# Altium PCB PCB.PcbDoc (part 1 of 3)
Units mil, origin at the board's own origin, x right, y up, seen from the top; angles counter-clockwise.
Board outline 5645.41 x 3720.47 mil, 4 copper layers (Top Layer, Signal Layer 1, Signal Layer 2, Bottom Layer), stack 61.2 mil thick; 253 components, 113 nets, 631 pads, 211 vias.
Unrouted connection lines stored in the file: 1.
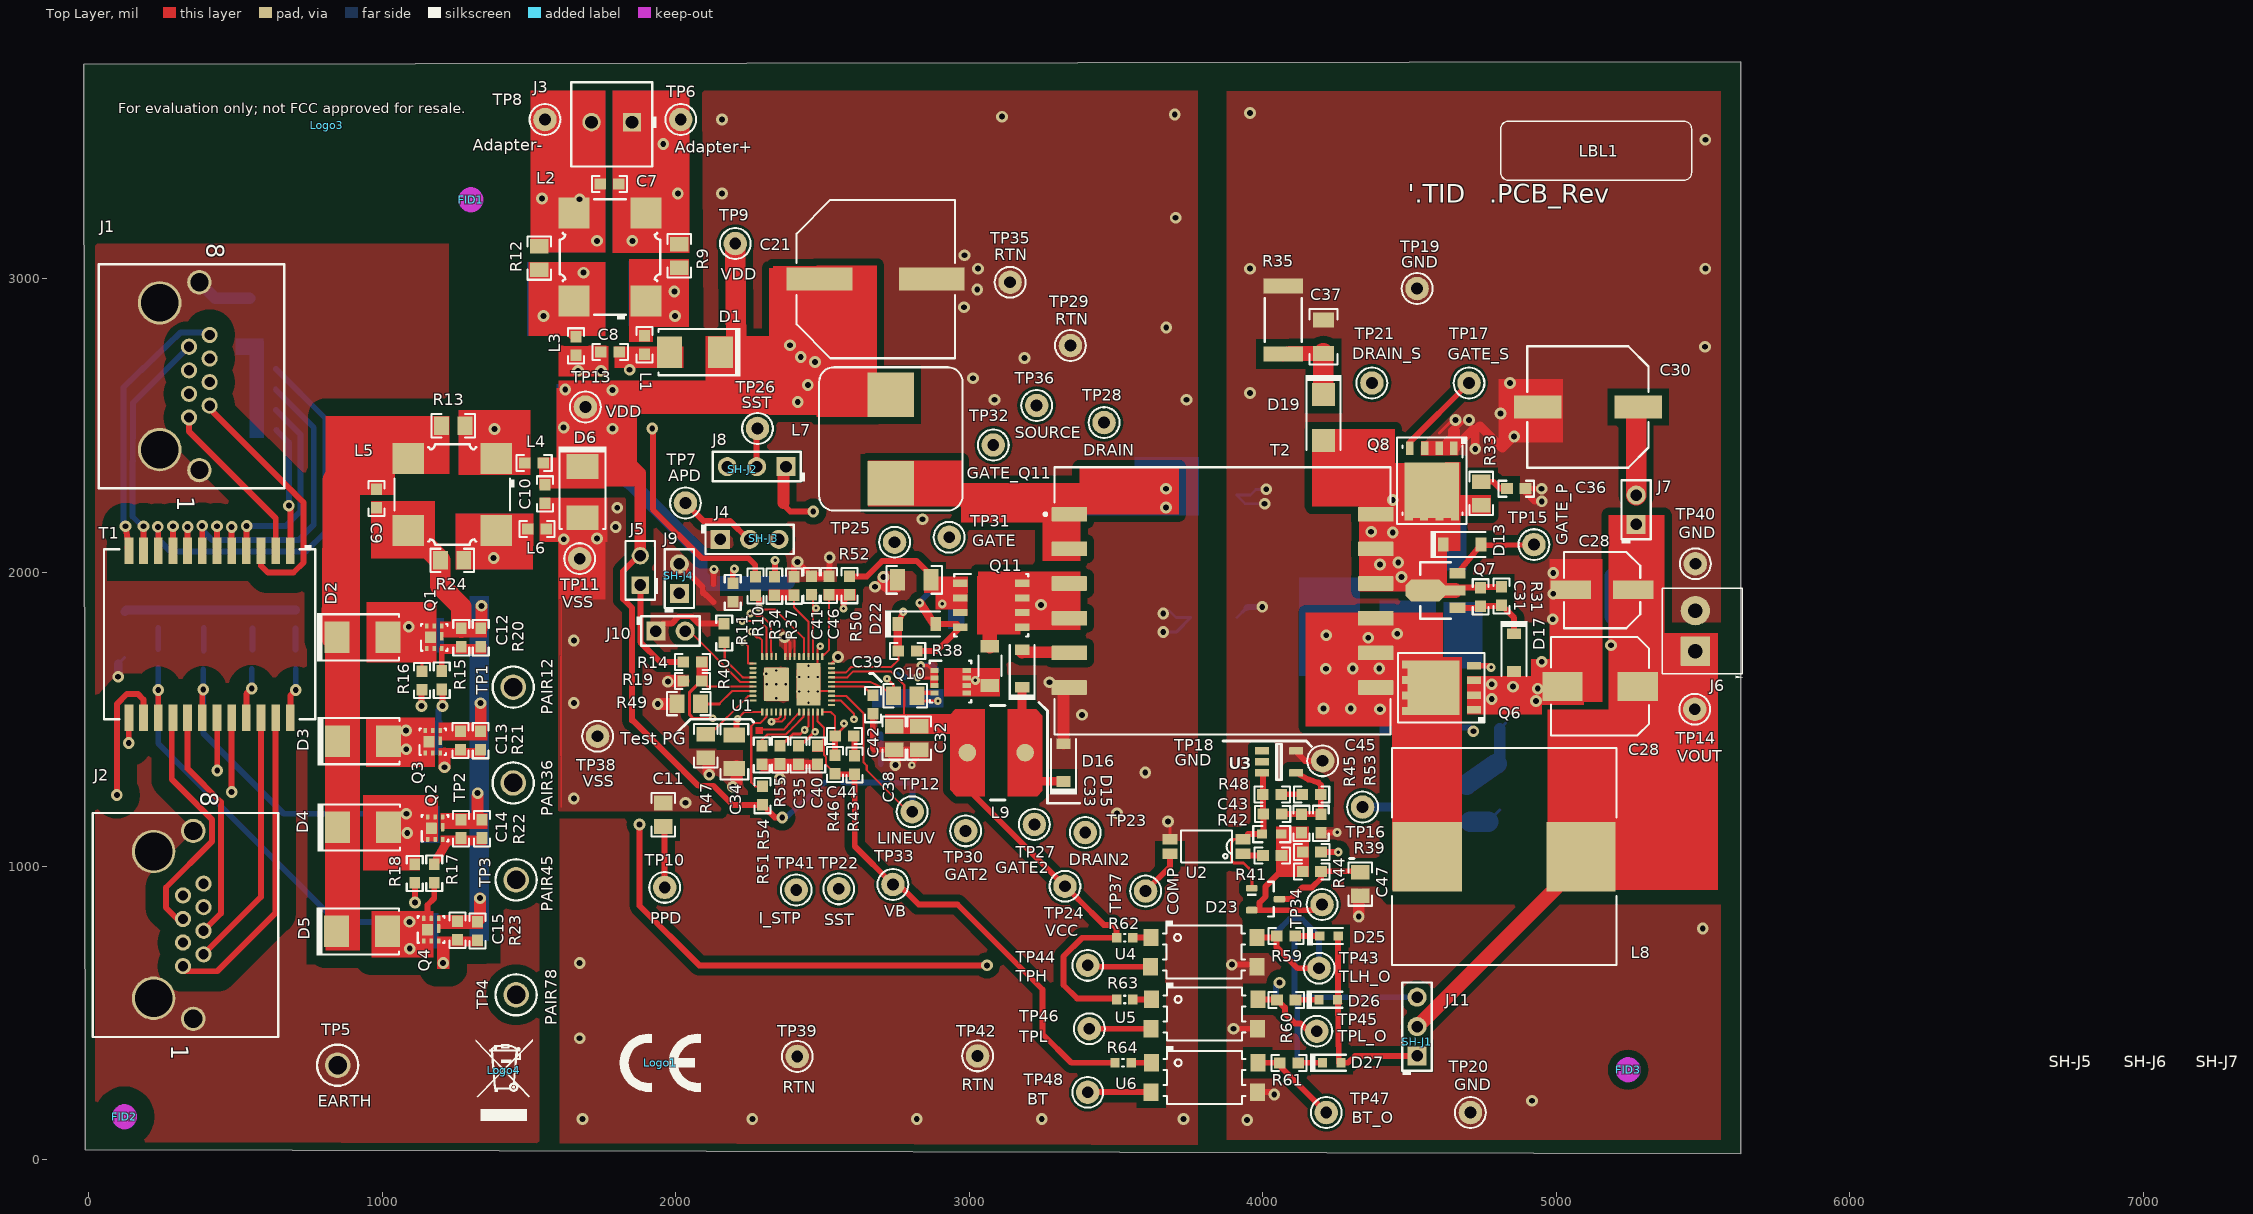
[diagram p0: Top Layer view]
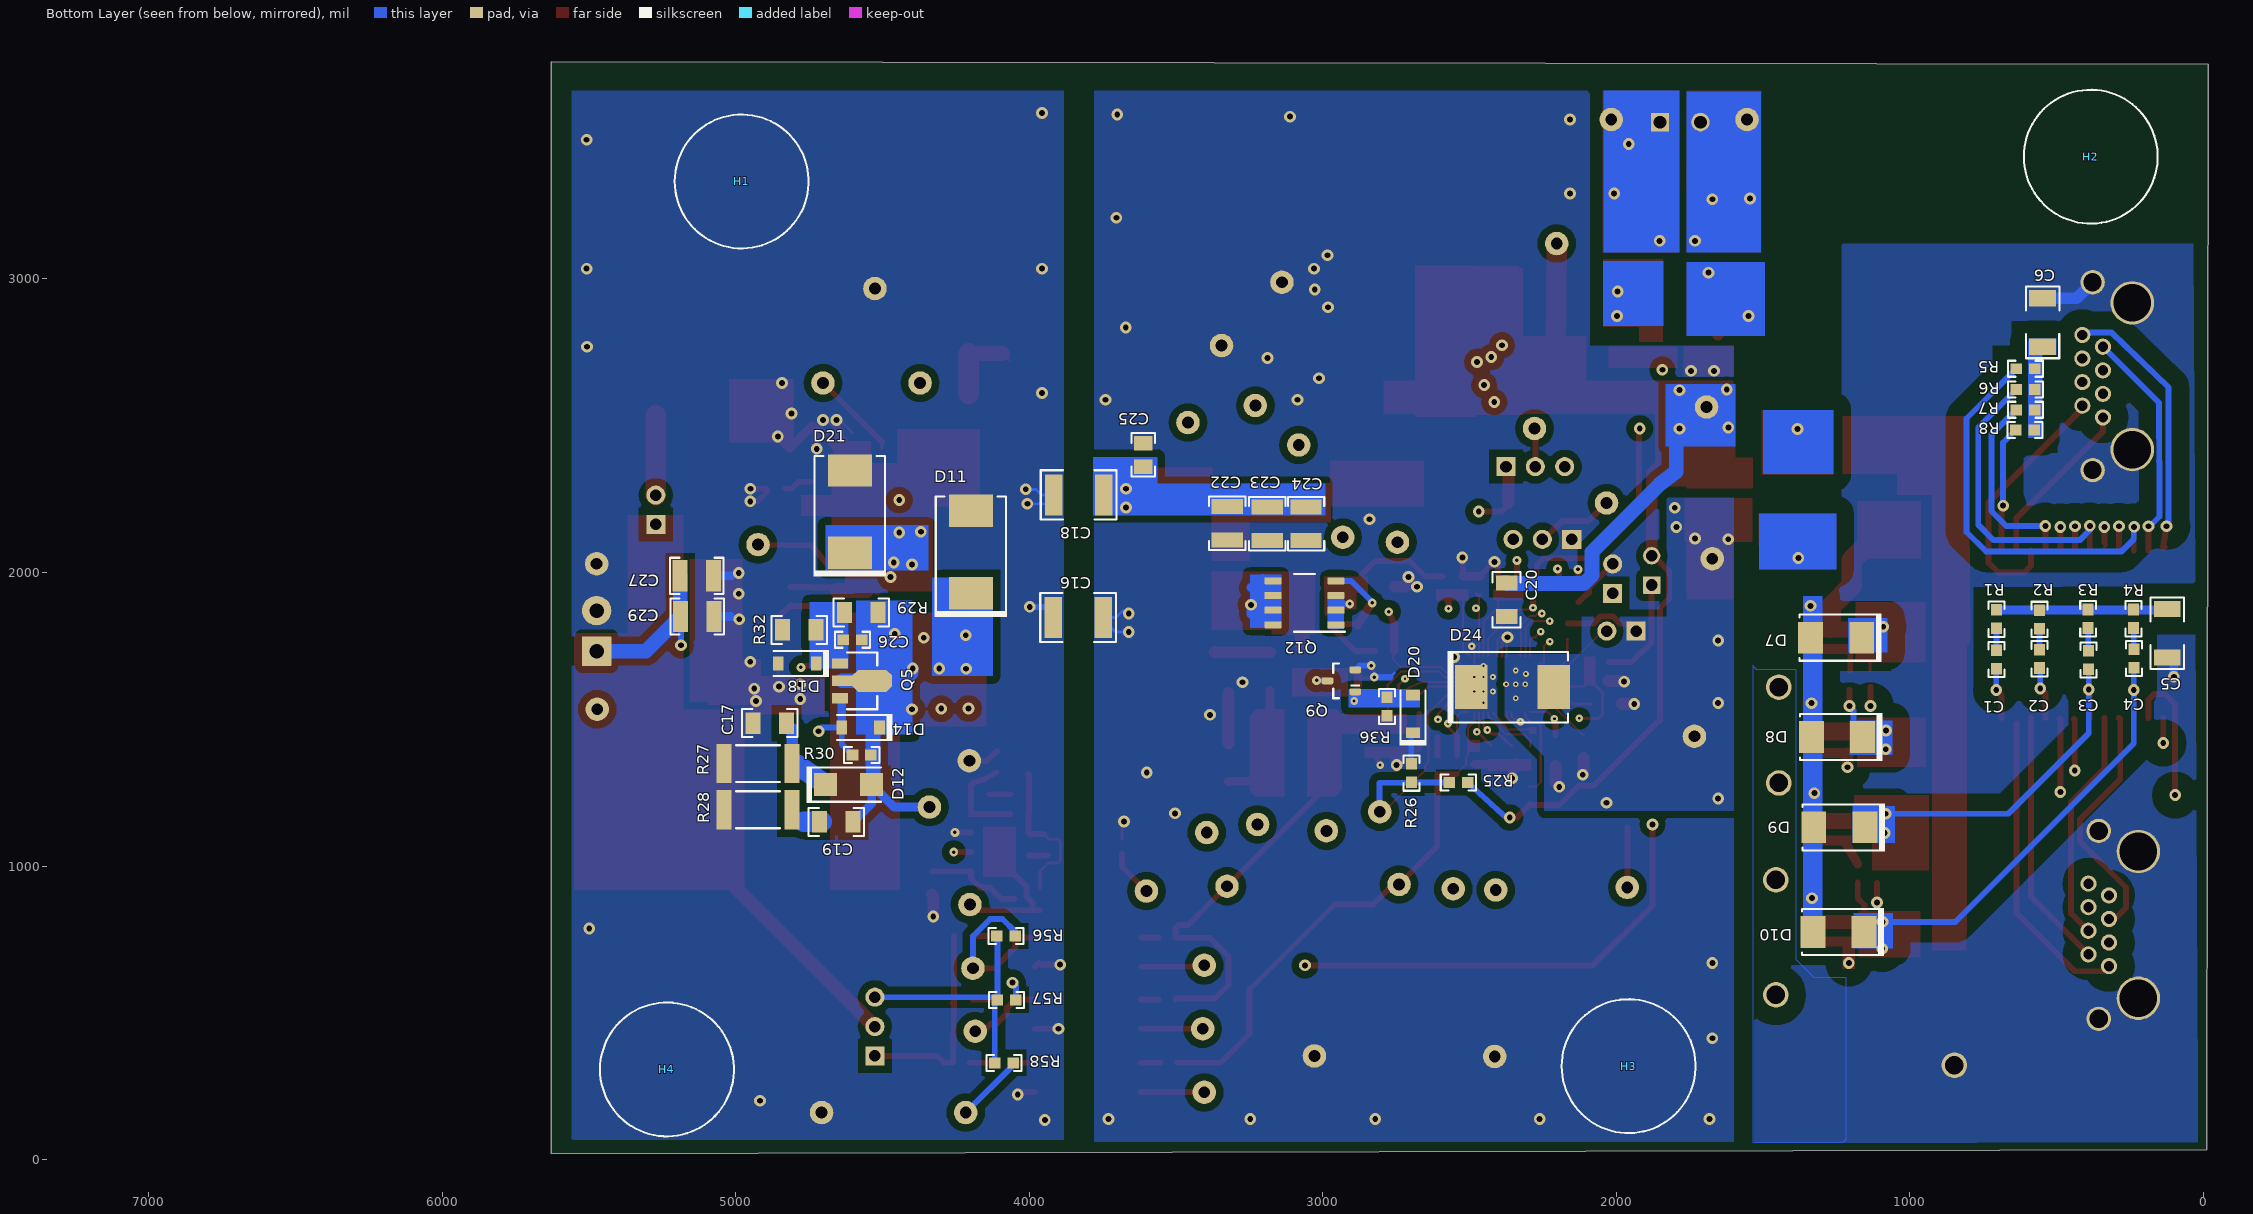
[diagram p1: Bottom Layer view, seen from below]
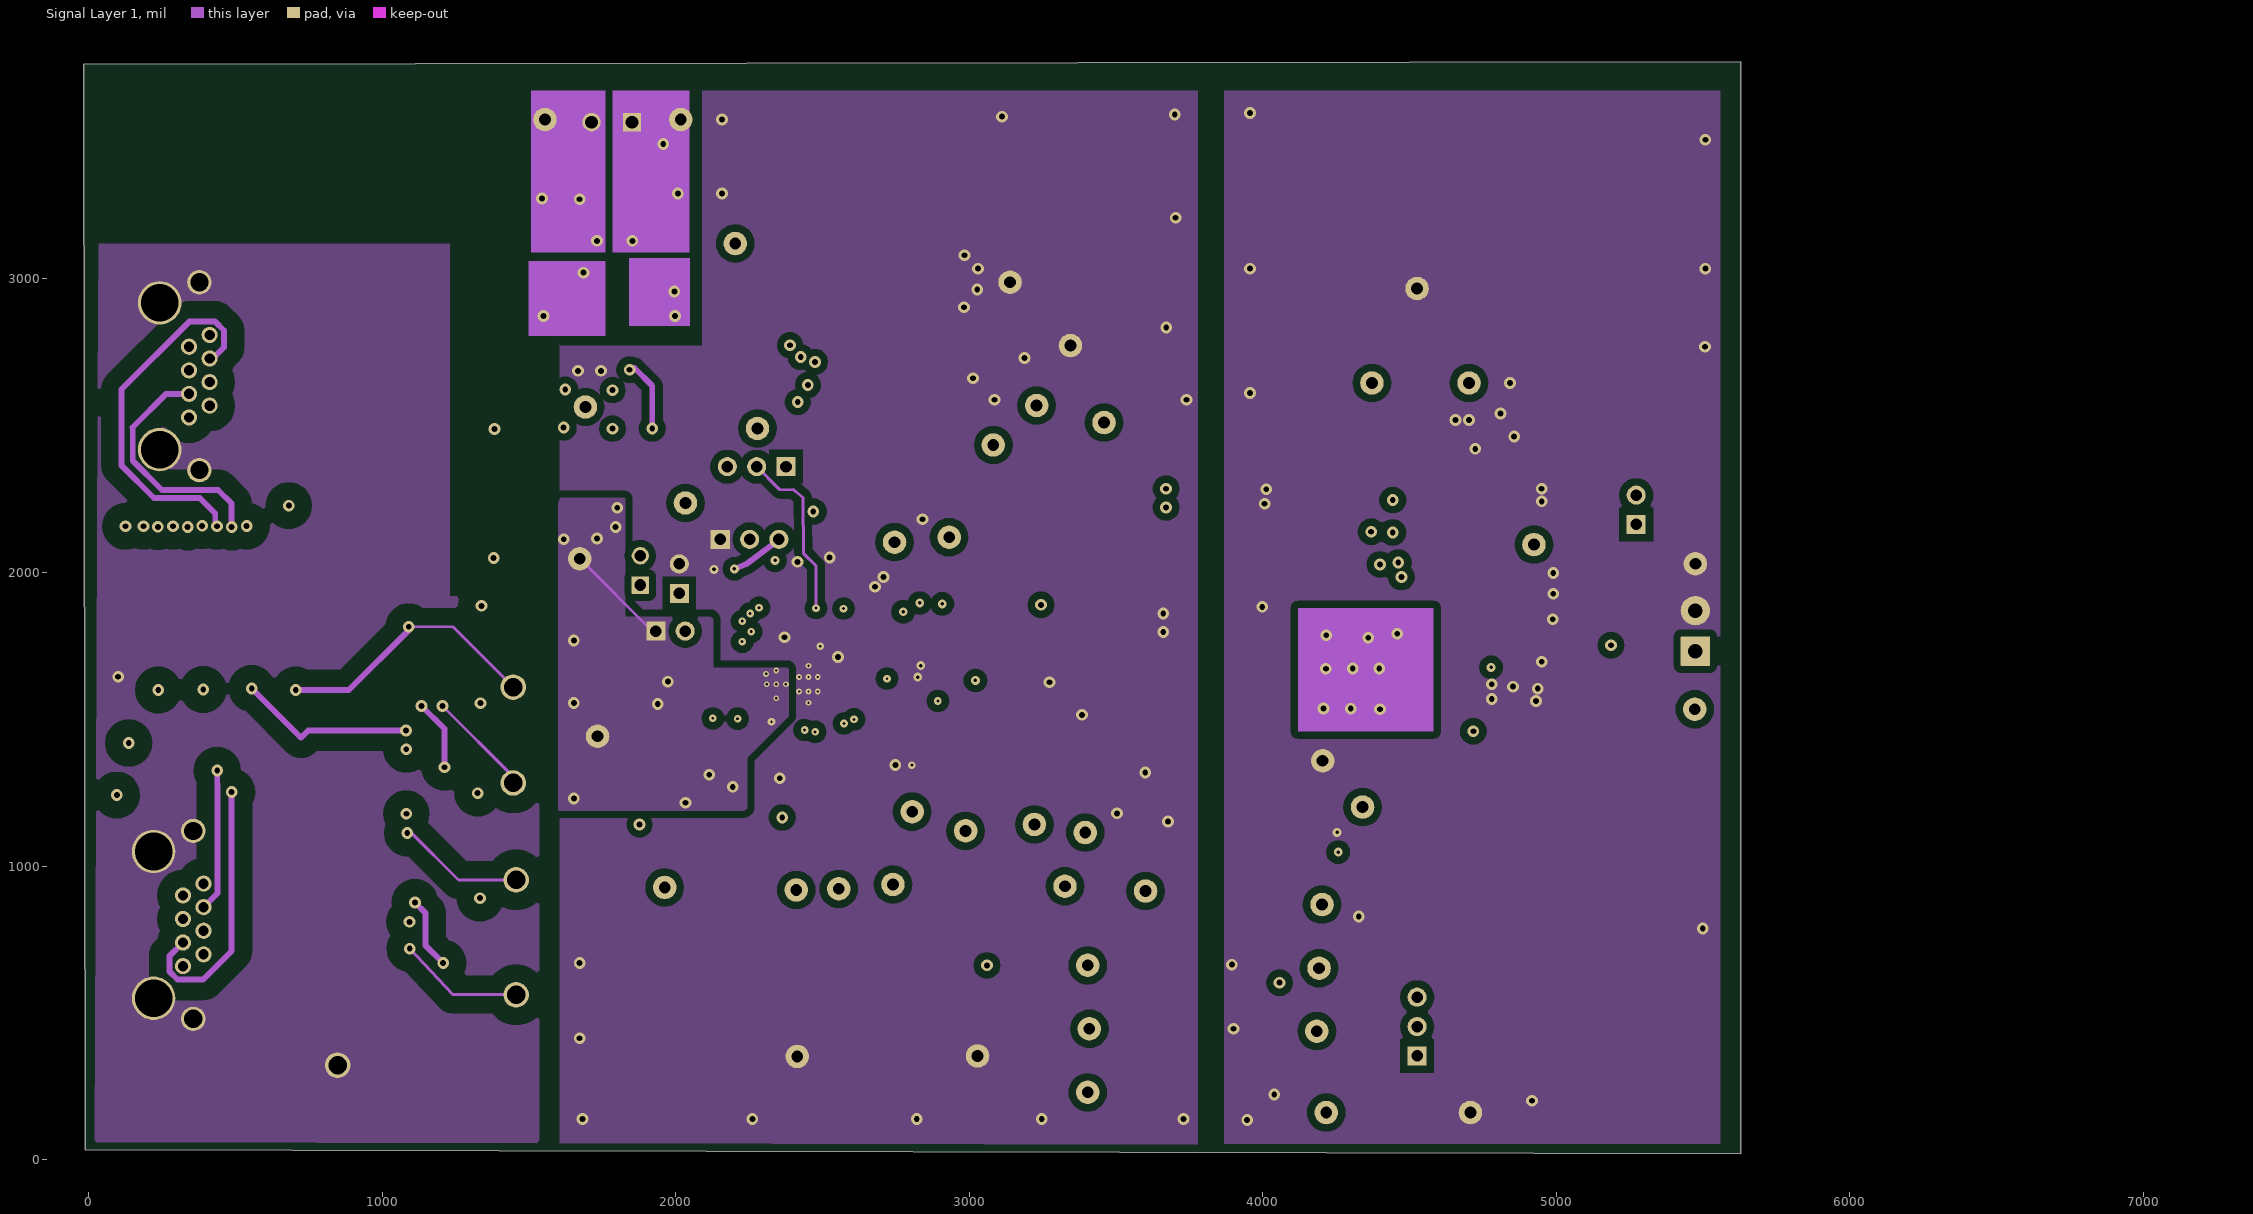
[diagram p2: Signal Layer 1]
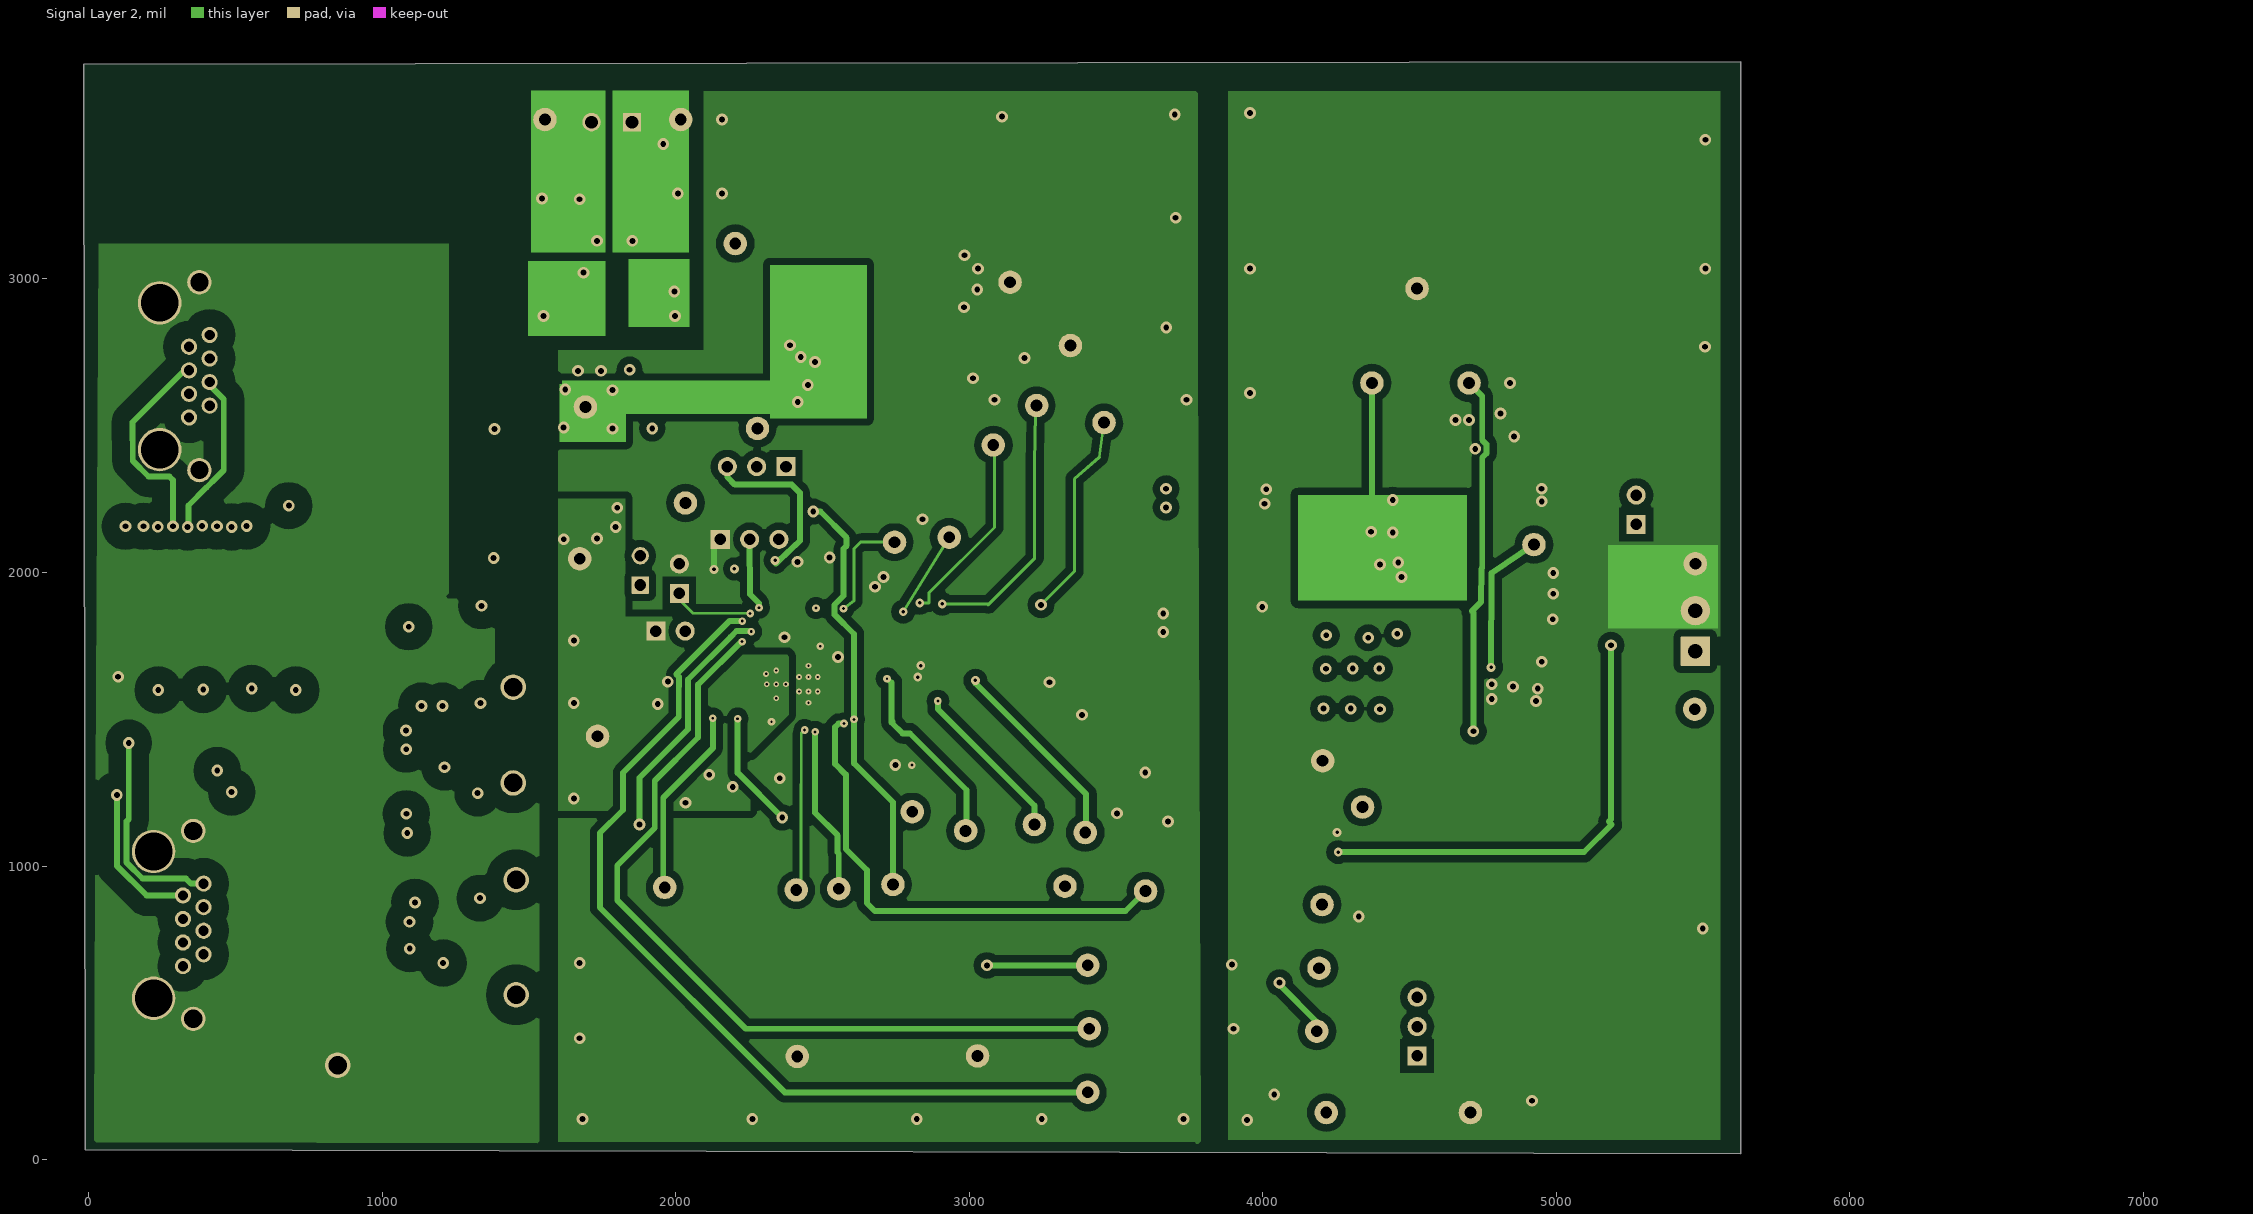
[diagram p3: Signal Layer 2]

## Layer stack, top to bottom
Top Solder: solder mask 0.4, Solder Resist, Dk 3.5
Top Layer: signal copper 2.8
Dielectric 1: prepreg 15, FR-4, Dk 4.8
Signal Layer 1: signal copper 2.8
Dielectric 2: core 20, FR-4, Dk 4.2
Signal Layer 2: signal copper 2.8
Dielectric 3: prepreg 15, FR-4, Dk 4.2
Bottom Layer: signal copper 2.8
Bottom Solder: solder mask 0.4, Solder Resist, Dk 3.5

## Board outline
-10.71,33.26 -16.35,3732 5629.06,3740.16 5629.06,19.68

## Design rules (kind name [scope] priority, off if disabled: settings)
AcuteAngle [All] p1: minimum=4.50000000000000E+0001 checktracksonly=FALSE
AssemblyTestPointUsage [All] p1: valid=2
BoardOutlineClearance BoardOutlineClearance_MountingHoles [OnCopper and InComponentClass('Mounting Holes')] p1: gap=39.37 ignorepadtopadclearanceinfootprint=FALSE
BoardOutlineClearance BoardOutlineClearance_Poly [OnCopper and IsPoly] p2: gap=25 ignorepadtopadclearanceinfootprint=FALSE
BoardOutlineClearance [OnCopper and Not InComponentClass('Logo') and not InComponentClass('FiducialMark') and not InRegion(1000,500,4000,800) and not InPoly] p3: gap=75 ignorepadtopadclearanceinfootprint=FALSE
Clearance Clearance_14 [InNamedPolygon('BOTTOM_LAYER_EARTH_P016')] p1: gap=60 ignorepadtopadclearanceinfootprint=FALSE
Clearance Clearance_13 [InNamedPolygon('SIGNAL_LAYER_1_EARTH_P014')] p2: gap=60 ignorepadtopadclearanceinfootprint=FALSE
Clearance Clearance_12 [InNamedPolygon('BOTTOM_LAYER_EARTH_P013')] p3: gap=60 ignorepadtopadclearanceinfootprint=FALSE
Clearance Clearance_11 [InNamedPolygon('SIGNAL_LAYER_2_EARTH_P012')] p4: gap=60 ignorepadtopadclearanceinfootprint=FALSE
Clearance Clearance_10 [InNamedPolygon('TOP_LAYER_EARTH_P015')] p5: gap=60 ignorepadtopadclearanceinfootprint=FALSE
Clearance Clearance_9 [InNamedPolygon('TOP_LAYER_EARTH_P015')] p6: gap=60 ignorepadtopadclearanceinfootprint=FALSE
Clearance Clearance_8 [InNamedPolygon('TOP_LAYER_EARTH_P015')] p7: gap=10 ignorepadtopadclearanceinfootprint=FALSE except(0: Arc-Hole Track-Hole SMDPad-Hole THPad-Hole Via-Hole Fill-Hole Poly-Hole Region-Hole Text-Hole)
Clearance "60 Mils_1" [InNamedPolygon('SIGNAL_LAYER_1_EARTH_P014')] p8: gap=10 ignorepadtopadclearanceinfootprint=FALSE except(0: Arc-Hole Track-Hole SMDPad-Hole THPad-Hole Via-Hole Fill-Hole Poly-Hole Region-Hole Text-Hole)
Clearance "60 Mils" [InNamedPolygon('SIGNAL_LAYER_2_EARTH_P012')] p9: gap=10 ignorepadtopadclearanceinfootprint=FALSE except(0: Arc-Hole Track-Hole SMDPad-Hole THPad-Hole Via-Hole Fill-Hole Poly-Hole Region-Hole Text-Hole)
Clearance Clearance_7 [InNamedPolygon('BOTTOM_LAYER_EARTH_P032')] p10: gap=10 ignorepadtopadclearanceinfootprint=FALSE except(0: Arc-Hole Track-Hole SMDPad-Hole THPad-Hole Via-Hole Fill-Hole Poly-Hole Region-Hole Text-Hole)
Clearance Clearance_6 [InNamedPolygon('TOP_LAYER_EARTH_P030')] p11: gap=10 ignorepadtopadclearanceinfootprint=FALSE except(0: Arc-Hole Track-Hole SMDPad-Hole THPad-Hole Via-Hole Fill-Hole Poly-Hole Region-Hole Text-Hole)
Clearance Clearance_5 [InNamedPolygon('BOTTOM_LAYER_EARTH_P032')] p12: gap=10 ignorepadtopadclearanceinfootprint=FALSE except(0: Arc-Hole Track-Hole SMDPad-Hole THPad-Hole Via-Hole Fill-Hole Poly-Hole Region-Hole Text-Hole)
Clearance Clearance_4 [InNamedPolygon('TOP_LAYER_EARTH_P030')] p13: gap=10 ignorepadtopadclearanceinfootprint=FALSE except(0: Arc-Hole Track-Hole SMDPad-Hole THPad-Hole Via-Hole Fill-Hole Poly-Hole Region-Hole Text-Hole)
Clearance Clearance_3 [InNamedPolygon('SIGNAL_LAYER_1_EARTH_P014')] p14: gap=10 ignorepadtopadclearanceinfootprint=FALSE except(0: Arc-Hole Track-Hole SMDPad-Hole THPad-Hole Via-Hole Fill-Hole Poly-Hole Region-Hole Text-Hole)
Clearance Clearance_2 [InNamedPolygon('SIGNAL_LAYER_2_EARTH_P012')] p15: gap=10 ignorepadtopadclearanceinfootprint=FALSE except(0: Arc-Hole Track-Hole SMDPad-Hole THPad-Hole Via-Hole Fill-Hole Poly-Hole Region-Hole Text-Hole)
Clearance Clearance_1 [InNamedPolygon('BOTTOM_LAYER_EARTH_P032')] p16: gap=10 ignorepadtopadclearanceinfootprint=FALSE except(0: Arc-Hole Track-Hole SMDPad-Hole THPad-Hole Via-Hole Fill-Hole Poly-Hole Region-Hole Text-Hole)
Clearance Clearance_Keepouts [((IsTrack Or IsArc) And Not InPoly) And IsFree and IsKeepOut vs ((IsTrack Or IsArc) And Not InPoly) And IsFree and IsKeepOut] p17: gap=0 ignorepadtopadclearanceinfootprint=FALSE
Clearance Clearance_Poly [InPolygon] p18: gap=25 ignorepadtopadclearanceinfootprint=TRUE
Clearance Clearance_FiducialMark [IsKeepOut and InComponentClass('FiducialMark') vs IsPad and InComponentClass('FiducialMark')] p19: gap=0 ignorepadtopadclearanceinfootprint=FALSE
Clearance [All] p20: gap=7.87 ignorepadtopadclearanceinfootprint=TRUE
ComponentClearance ComponentClearance_MountingHoles_FiducialMarks [InComponentClass('Mounting Holes') vs InComponentClass('FiducialMark')] p1: gap=50 collisioncheckmode=3 verticalgap=10 showdistances=FALSE
ComponentClearance ComponentClearance_Shunt [InComponentClass('Header') vs InComponentClass('Shunt')] p2: gap=0 collisioncheckmode=3 verticalgap=0 showdistances=FALSE
ComponentClearance ComponentClearance_Logo [InComponentClass('Logo')] p3: gap=50 collisioncheckmode=3 verticalgap=10 showdistances=FALSE
ComponentClearance ComponentClearance_ScrewToNut [(HasFootprint('NY PMS 440 0025 PH')) vs (HasFootprint('Keystone_1902C'))] p4: gap=5 collisioncheckmode=3 verticalgap=10 showdistances=FALSE
ComponentClearance ComponentClearance_MountingHoles [InComponentClass('Mounting Holes')] p5: gap=250 collisioncheckmode=3 verticalgap=100000 showdistances=FALSE
ComponentClearance ComponentClearance_SmallPassives [HasFootprint('0201*') or HasFootprint('0402*') or HasFootprint('0508') or HasFootprint('0603*') or HasFootprint('0612') or HasFootprint('0805*') or HasFootprint('0815*') or HasFootprint('0830*') or HasFootprint('1206*') or HasFootprint('1210*') or HasFootprint('1808*') or HasFootprint('1812*') or HasFootprint('1825*') or HasFootprint('2010*') or HasFootprint('2220*') or HasFootprint('2225*') or HasFootprint('2512*') or HasFootprint('2728*') or HasFootprint('3518*') vs HasFootprint('0201*') or HasFootprint('0402*') or HasFootprint('0508') or HasFootprint('0603*') or HasFootprint('0612') or HasFootprint('0805*') or HasFootprint('0815*') or HasFootprint('0830*') or HasFootprint('1206*') or HasFootprint('1210*') or HasFootprint('1808*') or HasFootprint('1812*') or HasFootprint('1825*') or HasFootprint('2010*') or HasFootprint('2220*') or HasFootprint('2225*') or HasFootprint('2512*') or HasFootprint('2728*') or HasFootprint('3518*')] p6: gap=14.96 collisioncheckmode=3 verticalgap=10 showdistances=FALSE
ComponentClearance ComponentClearance_THtoSMT [IsThruComponent vs IsSMTComponent] p7: gap=40 collisioncheckmode=3 verticalgap=30 showdistances=FALSE
ComponentClearance ComponentClearance_THtoTH [IsThruComponent vs IsThruComponent] p8: gap=30 collisioncheckmode=3 verticalgap=30 showdistances=FALSE
ComponentClearance [All] p9: gap=30 collisioncheckmode=3 verticalgap=10 showdistances=FALSE
DiffPairsRouting [All] p1: maxlimit=100 minlimit=10 mostfreqgap=10 toplayer_minwidth=15 toplayer_maxwidth=15 toplayer_prefwidth=15 midlayer1_minwidth=15 midlayer1_maxwidth=15 midlayer1_prefwidth=15 midlayer2_minwidth=15 midlayer2_maxwidth=15 midlayer2_prefwidth=15 bottomlayer_minwidth=15 bottomlayer_maxwidth=15 bottomlayer_prefwidth=15 maxuncoupledlength=1000
FabricationTestPointUsage TestPointUsage [All] p1: valid=2 allowmultiple=FALSE
FabricationTestpoint Testpoint [All] p1: side=3 testpointundercomponent=TRUE minsize=40 maxsize=100 preferedsize=60 minholesize=0 maxholesize=40 preferedholesize=32 testpointgrid=1 allowsidetop=TRUE allowsidebottom=TRUE usegrid=TRUE gridtolerance=0.01
FanoutControl Fanout_LCC [IsLCC] p1: bgadir=Out bgaviamode=Centered fanoutstyle=Auto fanoutdirection=Alternating viagrid=1 // Fanout_LCC (Default Rule)
FanoutControl Fanout_BGA [IsBGA] p2: bgadir=Out bgaviamode=Centered fanoutstyle=Auto fanoutdirection=Alternating viagrid=1 // Fanout_BGA (Default Rule)
FanoutControl Fanout_Default [All] p4: bgadir=Out bgaviamode=Centered fanoutstyle=Auto fanoutdirection=Alternating viagrid=1 // Fanout_Default (Default Rule)
FanoutControl Fanout_Small [(CompPinCount < 5)] p5: bgadir=Out bgaviamode=Centered fanoutstyle=Auto fanoutdirection=OutThenIn viagrid=1 // Fanout_Small (Default Rule)
HoleSize [All] p1: absolutevalues=TRUE maxlimit=251 minlimit=7.87 maxpercent=80.000 minpercent=20.000
MinimumAnnularRing MinimumAnnularRing_ThermalPadVias [IsVia and InAnyComponent] p1: minimumring=5.91
MinimumAnnularRing [All] p2: minimumring=7.87
MinimumSolderMaskSliver MinimumSolderMaskSliver_Logo [InComponentClass('Logo') vs InComponentClass('Logo')] p1: minsoldermaskwidth=0.7
MinimumSolderMaskSliver [All] p2: minsoldermaskwidth=3.94
PlaneConnect [All] p1: planeconnectstyle=Relief reliefexpansion=10 reliefentries=4 reliefconductorwidth=10 reliefairgap=10
PolygonConnect [All] p1: connectstyle=Direct reliefconductorwidth=10 reliefentries=4 polygonreliefangle="90 Angle" airgapwidth=10
RoutingVias ThermalPadVias [IsVia and InAnyComponent] p1: holewidth=7.87 width=19.68 viastyle="Through Hole" minholewidth=7.87 minwidth=19.68 maxholewidth=12.99 maxwidth=23.62
RoutingVias [All] p2: holewidth=16 width=34 viastyle="Through Hole" minholewidth=7.87 minwidth=26 maxholewidth=40 maxwidth=65
SilkToBoardRegionClearance [Not ((IsComment or IsDesignator) And (Hide <> 'False')) and not InRegion(1000,500,4000,800)] p1:
SilkToSilkClearance SilkToSilkClearance_Pb-FreeLogo [(HasFootprint('Pb-Free_Overlay_Medium') OR HasFootprint('Pb-Free_Overlay_Small')) vs (HasFootprint('Pb-Free_Overlay_Medium') OR HasFootprint('Pb-Free_Overlay_Small'))] p1: silktosilkclearance=0
SilkToSilkClearance [All] p2: silktosilkclearance=3.94
SilkToSolderMaskClearance SilkToComponentPadClearance [(IsPad or IsFill or IsRegion) and InAnycomponent] p1: minsilkscreentomaskgap=5 clearancetoexposedcopper=TRUE
SilkToSolderMaskClearance "Silk to Solder Mask Opening" [All] p2: minsilkscreentomaskgap=3.94 clearancetoexposedcopper=FALSE
SolderMaskExpansion [All] p1: expansion=1.97
UnRoutedNet [All] p1: checkbadconnections=TRUE
Width [All] p1: maxlimit=100 minlimit=6 preferedwidth=10 checkconnectedcopper=TRUE
14 further rules are at their usual default settings.

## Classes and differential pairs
component class Shunt: SH-J1 SH-J2 SH-J3 SH-J4 SH-J5 SH-J6 SH-J7
component class "TPS23730 Page 1 Input Power": C1 C2 C3 C4 C5 C6 C7 C8 C9 C10 C11 C12 C13 C14 C15 D1 D2 D3 D4 D5 D6 D7 D8 D9 D10 J1 J2 J3 J4 J5 L1 L2 L3 L4 L5 L6 Q1 Q2 Q3 Q4 R1 R2 R3 R4 R5 R6 R7 R8 R9 R10 R11 R12 R13 R14 R15 R16 R17 R18 R19 R20 R21 R22 R23 R24 T1 TP1 TP2 TP3 TP4 TP5 TP6 TP7 TP8 TP9 TP10 TP11
component class "Power Stage": C16 C17 C18 C19 C20 C21 C22 C23 C24 C25 C26 C27 C29 C30 C31 C32 C33 C34 C35 C36 C37 C38 C39 C40 C41 C42 C43 C44 C45 C46 C47 D11 D12 D13 D14 D15 D16 D17 D18 D19 D20 D21 D22 D23 D24 D25 D26 D27 J6 J7 J8 J9 J10 J11 L7 L8 L9 Q5 Q6 Q7 Q9 Q10 Q11 Q12 R25 R26 R27 R28 R29 R30 R31 R32 R33 R34 R35 R36 R37 R38 R39 R40 R41 R42 R43 R44 R45 R46 R47 R48 R49 R50 R51 R52 R53 R54 R55 R56 R57 R58 R59 R60 R61 R62 R63 R64 TP12 TP13 TP14 TP15 TP16 TP17 TP18 TP19 TP20 TP21 TP22 TP23 TP24 TP25 TP26 TP27 TP28 TP29 TP30 TP31 TP32 TP33 TP34 TP35 TP36 TP37 TP38 TP39 TP40 TP41 TP42 TP43 TP44 TP45 TP46 TP47 TP48 U1 U2 U4 U5 U6
component class Header: J4 J5 J7 J8 J9 J10 J11
component class Hardware: FID1 FID2 FID3 H1 H2 H3 H4 LBL1 Logo1 Logo3 Logo4 SH-J1 SH-J2 SH-J3 SH-J4 SH-J5 SH-J6 SH-J7 ZZ1 ZZ2 ZZ3 ZZ4
component class FiducialMark: FID1 FID2 FID3
component class AssemblyNote: ZZ1 ZZ2 ZZ3 ZZ4
component class Label: LBL1

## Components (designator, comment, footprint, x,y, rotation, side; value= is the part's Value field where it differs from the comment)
C1 "CGA3E2X7R2A103K080AA" 0603 705.58,1703.55 r270 bottom value=0.01uF
C2 "CGA3E2X7R2A103K080AA" 0603 559.05,1706.06 r270 bottom value=0.01uF
C3 "CGA3E2X7R2A103K080AA" 0603 391.73,1702.14 r270 bottom value=0.01uF
C4 "CGA3E2X7R2A103K080AA" 0603 236.43,1707.1 r270 bottom value=0.01uF
C5 "GR442QR73D102KW01L" 1808 123.15,1793.21 r90 bottom value=1000pF
C6 "GR442QR73D102KW01L" 1808 548.29,2851.9 r270 bottom value=1000pF
C7 "C1608X7R2A102K080AA" 0603 1774.96,3323.43 r180 top value=1000pF
C8 "C1608X7R2A102K080AA" 0603 1777.28,2750.6 r180 top value=1000pF
C9 "C1608X7R2A102K080AA" 0603 981,2252.22 r270 top value=1000pF
C10 "C1608X7R2A102K080AA" 0603 1554.47,2267.96 r270 top value=1000pF
C11 "08051C471KAT2A" 0805_HV 1958.66,1174.89 r90 top value=470pF
C12 "885012006060" 0603 1269.83,1777.85 r90 top value=330pF
C13 "885012006060" 0603 1267.4,1427.58 r90 top value=330pF
C14 "885012006060" 0603 1269.22,1126.86 r90 top value=330pF
C15 "885012006060" 0603 1256.76,780.9 r90 top value=330pF
C16 "C4532X7R3D222K130KA" 1812_HV 3834.05,1846.6 r180 bottom value=2200pF
C17 "CGA5H2X7R2A473K115AA" 1206 4884.22,1486.71 r180 bottom value=0.047uF
C18 "C4532X7R3D222K130KA" 1812_HV 3832.29,2264.38 r180 bottom value=2200pF
C19 "12061C102KAT2A" 1206 4657.49,1150.17 r180 bottom value=1000pF
C20 "GRM319R72A104KA01D" 1206 2373.91,1907.27 r270 bottom value=0.1uF
C21 "EEV-FK2A680Q" SM_RADIAL_H13 2681.9,2999.72 r0 top value=68uF
C22 "GRM32ER72A225KA35L" 1210_270 3325.7,2167.32 r270 bottom value=2.2uF
C23 "GRM32ER72A225KA35L" 1210_270 3189.76,2166.54 r270 bottom value=2.2uF
C24 "GRM32ER72A225KA35L" 1210_270 3057.24,2166.54 r270 bottom value=2.2uF
C25 "GRM21BR72A104KAC4L" 0805_HV 3612.2,2400.63 r90 bottom value=0.1uF
C26 "06033C101KAT2A" 0603 4602.79,1770.91 r180 bottom value=100pF
C27 "GRM32EC70J107ME15L" 1210_270 5132.73,1988.59 r0 bottom value=100uF
C27 "GMK325BJ226MM-P" 1210 5132.73,1988.59 r0 bottom value=22uF
C28 "UUD0J471MNL1GS" SM_RADIAL_8MM 5149.73,1612.23 r180 top value=470uF
C28 "16SVP39M" SM_RADIAL_6.3AMM 5156.7,1940.6 r180 top value=39uF
C29 "GRM32EC70J107ME15L" 1210_270 5132.01,1849.96 r0 bottom value=100uF
C29 "GMK325BJ226MM-P" 1210 5132.01,1849.96 r0 bottom value=22uF
C30 "EEEFPE561UAP" Panasonic_G 5108.27,2563.86 r180 top value=560uF
C31 "06033C101KAT2A" 0603 4743.12,1917.05 r270 top value=100pF
C32 "GRM21BR71E105KA99L" 0805_HV 2830.91,1436.08 r270 top value=1uF
C33 "GRM31CR72E473KW03L" 1206_180 3070.8,1682.21 r270 top value=0.047uF
C34 "GRM319R72A104KA01D" 1206 2200.07,1388.67 r270 top value=0.1uF
C35 "GRM188R71H473KA61D" 0603 2419.04,1377.9 r90 top value=0.047uF
C36 "CGA3E2X7R2A102K080AA" 0603 4864.17,2285.39 r180 top value=1000pF
C37 "CGA5H2X7R2A473K115AA" 1206 4207.38,2803.15 r270 top value=0.047uF
C38 "GCM21BR71H104KA37K" 0805_HV 2744.29,1436.08 r270 top value=0.1uF
C39 "C2012X5R1H224K125AA" 0805_HV 2782.68,1580.63 r180 top value=0.22uF
C40 "CGA3E2X7R1E104K080AA" 0603 2482.83,1378.31 r90 top value=0.1uF
C41 "C0603C222K5RAC" 0603 2463.64,1955.69 r90 top value=2200pF
C42 "C0603C104J3RACTU" 0603 2671.97,1549.87 r90 top value=0.1uF
C43 "06033C101KAT2A" 0603 4034.25,1177.37 r0 top value=100pF
C44 "GRM188R71C683KA01D" 0603 2575.17,1442.85 r0 top value=0.068uF
C45 "GRM188R71H392KA01D" 0603 4167.12,1244.3 r180 top value=3900pF
C46 "GRM1885C1H470JA01D" 0603 2523.35,1955.69 r90 top value=47pF
C47 "C2012X7R1H105K125AB" 0805_HV 4332.52,938.68 r270 top value=1uF
D1 "CMP-0028397-2" SMB 2066.78,2750.6 r180 top value=100V
D2 "B2100-13-F" SMB 932.75,1779.2 r0 top value=100V
D3 "B2100-13-F" SMB 934.72,1425.27 r0 top value=100V
D4 "B2100-13-F" SMB 935.56,1131.78 r0 top value=100V
D5 "B2100-13-F" SMB 932.02,777.45 r0 top value=100V
D6 "SMBJ58A-13-F" SMB 1683.07,2273.62 r270 top value=58V
D7 "CMP-0028397-2" SMB 1251.15,1777.85 r0 bottom value=100V
D8 "CMP-0028397-2" SMB 1249.15,1439.37 r0 bottom value=100V
D9 "CMP-0028397-2" SMB 1240.67,1131.78 r0 bottom value=100V
D10 "CMP-0028397-2" SMB 1243.09,775.12 r0 bottom value=100V
D11 "SMCJ60A" SMC 4199.08,2069.56 r90 bottom value=60V
D12 "MURA110T3G" SMA 4616.14,1277.5 r180 bottom value=100V
D13 "MMSD914T1G" SOD-123 4679.63,2095.04 r0 top value=100V
D14 "MMSD914T1G" SOD-123 4575.08,1471.95 r0 bottom value=100V
D15 "MMSD914T1G" SOD-123 3181.08,1673.04 r90 top value=100V
D16 "MMSD914T1G" SOD-123 3321.99,1352.47 r90 top value=100V
D17 "MMSZ5242B-7-F" SOD-123 4857.07,1727.09 r270 top value=12V
D18 "MMSZ5242B-7-F" SOD-123 4791.28,1689.47 r0 bottom value=12V
D19 "MURA110T3G" SMA 4207.38,2528.25 r270 top value=100V
D20 "MMSD914T1G" SOD-123 2693.4,1517.81 r90 bottom value=100V
D21 "SMCJ60A" SMC 4611.42,2207.36 r90 bottom value=60V
D22 "MMSD914T1G" SOD-123 2821.4,1824.04 r0 top value=100V
D23 "BAT54S-7-F" SOT-23 4010.28,886.87 r0 top value=30V
D24 "B3100-13-F" SMC 2353.85,1609.33 r180 bottom value=100V
D25 "150060YS75000" WL-SMCW_YELLOW 4226.02,761.54 r0 top value=Yellow
D26 "150060YS75000" WL-SMCW_YELLOW 4224.05,544.2 r0 top value=Yellow
D27 "150060YS75000" WL-SMCW_YELLOW 4236,329.52 r0 top value=Yellow
FID1 "Fiducial" Fiducial10-20 1302.63,3269.87 r0 top
FID2 "Fiducial" Fiducial10-20 122.15,145.78 r0 top
FID3 "Fiducial" Fiducial10-20 5245.2,305.89 r0 top
H1 "SJ-5303 (CLEAR)" Bumpon_SJ5003Transparent 4980.47,3332.26 r90 bottom
H2 "SJ-5303 (CLEAR)" Bumpon_SJ5003Transparent 383.86,3416.7 r180 bottom
H3 "SJ-5303 (CLEAR)" Bumpon_SJ5003Transparent 1958.66,318.09 r180 bottom
H4 "SJ-5303 (CLEAR)" Bumpon_SJ5003Transparent 5234.92,306.96 r180 bottom
J1 "1-406541-1" TEC_1-406541-1 349.61,2668.4 r270 top
J2 "1-406541-1" TEC_1-406541-1 328.87,799.11 r270 top
J3 "39357-0002" MOLEX_39357-0002 1782.66,3534.42 r180 top
J4 "5-146278-3" TE_5-146278-3 2252.24,2112.84 r0 top
J5 "PEC02SAAN" CONN_PEC02SAAN 1879.92,2007.09 r90 top
J6 "ED555/2DS" TERM_BLK_ED555-2DS 5474.53,1731.97 r90 top
J7 "5-146278-2" TE_5-146278-2 5272.85,2213.78 r90 top
J8 "5-146278-3" TE_5-146278-3 2276.29,2360.81 r180 top
J9 "5-146278-2" TE_5-146278-2 2012.89,1979.13 r90 top
J10 "5-146278-2" TE_5-146278-2 1982.68,1800.55 r0 top
J11 "5-146278-3" TE_5-146278-3 4526.26,453.06 r90 top
L1 "742792641" 0603 1894.16,2775.8 r270 top value="300 ohm"
L2 "744272251" WE-SL5 1776.53,3075.01 r180 top value=250uH
L3 "742792641" 0603 1661.01,2772.25 r270 top value="300 ohm"
L4 "742792641" 0603 1518.25,2373.57 r0 top value="300 ohm"
L5 "744272251" WE-SL5 1239.27,2265.99 r270 top value=250uH
L6 "742792641" 0603 1528.15,2148.8 r0 top value="300 ohm"
L7 "744325550" WE-HC6 2733.31,2455.19 r270 top value=5.5uH
L8 "74435571500" WE-HCB_1890 4823.27,1032.05 r0 top value=15uH
L9 "768775322" WE-PD2-L 3092.64,1386.08 r0 top value=2.2mH
LBL1 "THT-14-423-10" Label_650x200 5136.49,3436.88 r0 top
Logo1 "CE Mark" CE_Mark_5mm 1947.8,329.52 r0 top
Logo3 "FCC disclaimer" FCC_disclaimer 811.29,3522.93 r0 top
Logo4 "WEEE logo" WEEE_Minimum 1414.24,305.02 r0 top
Q1 "CSD19538Q2" DQK0006C 1177.83,1779.2 r90 top value=100V
Q2 "CSD19538Q2" DQK0006C 1180.64,1128.83 r90 top value=100V
Q3 "CSD19538Q2" DQK0006C 1172.71,1423.32 r90 top value=100V
Q4 "CSD19538Q2" DQK0006C 1167.32,783.32 r90 top value=100V
Q5 "FCX493TA" SOT-89-3 4570.36,1631.03 r180 bottom value="100 V"
Q6 "BSC105N10LSF G" PG-TDSON-8 4609.25,1607.21 r180 top value=100V
Q7 "FCX493TA" SOT-89-3 4589.73,1938.73 r180 top value="100 V"
Q8 "CSD18503Q5A" DQJ0008A 4578.76,2314.13 r270 top value=40V
Q8 "BSC105N10LSF G" PG-TDSON-8 4576.77,2311.96 r270 top value=100V
Q9 "SQ2337ES-T1_GE3" SOT-23 2937.07,1630.99 r0 bottom value=-80V
Q10 "FDMC2523P" MLP08S 2937.01,1628.16 r0 top value=-150V
Q11 "FDMS86250" TRANS_Fairchild_PQFN08A 3075.57,1888.45 r0 top value=150V
Q12 "SI4848DY-T1-E3" SOIC-8 3063.05,1896.58 r0 bottom value=150V
R1 "CRCW060375R0FKEA" 0603 705.58,1840.9 r90 bottom value=75.0
R2 "CRCW060375R0FKEA" 0603 559.05,1840.45 r90 bottom value=75.0
R3 "CRCW060375R0FKEA" 0603 392.6,1842.42 r90 bottom value=75.0
R4 "CRCW060375R0FKEA" 0603 237.6,1842.42 r90 bottom value=75.0
R5 "CRCW060375R0FKEA" 0603 606.3,2694.15 r180 bottom value=75.0
R6 "CRCW060375R0FKEA" 0603 606.3,2623.29 r180 bottom value=75.0
R7 "CRCW060375R0FKEA" 0603 606.3,2554.39 r180 bottom value=75.0
R8 "CRCW060375R0FKEA" 0603 608.27,2485.49 r180 bottom value=75.0
R9 "PMR10EZPJ000" 0805_HV 2012.89,3078.69 r270 top value=0
R10 "CRCW0603100KFKEA" 0603 2272.29,1953.96 r90 top value=100k
R11 "CRCW06034K42FKEA" 0603 2194.88,1931.68 r90 top value=4.42k
R12 "PMR10EZPJ000" 0805_HV 1535.43,3071.47 r270 top value=0
R13 "PMR10EZPJ000" 0805_HV 1242.56,2500 r0 top value=0
R14 "CRCW0603100KFKEA" 0603 2057.53,1694.9 r0 top value=100k
R15 "CRCW06031M00FKEA" 0603 1203.42,1632.95 r270 top value=1.00Meg
R16 "CRCW06031M00FKEA" 0603 1136.5,1632.39 r90 top value=1.00Meg
R17 "CRCW06031M00FKEA" 0603 1177.83,975.23 r270 top value=1.00Meg
R18 "CRCW06031M00FKEA" 0603 1111.38,974.41 r90 top value=1.00Meg
R19 "CRCW060315K0FKEA" 0603 2057.53,1630.93 r0 top value=15.0k
R20 "CRCW0603232KFKEA" 0603 1336.3,1777.85 r270 top value=232k
R21 "CRCW0603232KFKEA" 0603 1336.15,1427.06 r270 top value=232k
R22 "CRCW0603232KFKEA" 0603 1339.95,1126.86 r270 top value=232k
R23 "CRCW0603232KFKEA" 0603 1325.65,778.93 r270 top value=232k
R24 "PMR10EZPJ000" 0805_HV 1238.86,2040.95 r0 top value=0
R25 "CRCW0603110KFKEA" 0603 2538.52,1284.56 r180 bottom value=110k
R26 "CRCW060310K0FKEA" 0603 2698.84,1316.32 r270 bottom value=10.0k
R27 "CRCW251210K0JNEG" 2512 4924.55,1348.92 r0 bottom value=10k
R28 "CRCW2512100RJNEG" 2512 4924.55,1191.44 r0 bottom value=100
R29 "CRCW12064K02FKEA" 1206 4573.27,1863.88 r180 bottom value=4.02k
R30 "CRCW060310R0FKEAHP" 0603 4571.3,1377.95 r180 bottom value=10.0
R31 "CRCW06032K00JNEA" 0603 4814.54,1919.56 r90 top value=2.0k
R32 "CRCW12068K06FKEA" 1206 4783.9,1804.47 r180 bottom value=8.06k
R33 "ERJ-6RQF5R1V" 0805_HV 4745.64,2269.32 r90 top value=5.10
R34 "RC0603FR-07237KL" 0603 2336.27,1953.59 r270 top value=237k
R35 "CRCW251210K0JNEG" 2512 4069.97,2860.44 r90 top value=10k
R36 "CRCW060310K0FKEA" 0603 2782.06,1543.56 r90 bottom value=10.0k
R37 "CRCW060360K4FKEA" 0603 2403.18,1953.59 r270 top value=60.4k
R38 "CRCW060310R0FKEA" 0603 2790.74,1731.98 r0 top value=10.0
R39 "RC0603FR-0749R9L" 0603 4167.57,1047.45 r0 top value=49.9
R40 "CRCW060349K9FKEA" 0603 2165.79,1794.14 r270 top value=49.9k
R41 "CRCW06032K00FKEA" 0603 4032.82,1035.99 r0 top value=2.00k
R42 "Y16362K00000F9R" VSMP_0603 4031.14,1108.47 r0 top value=2.00k
R43 "CRCW0603499RFKEA" 0603 2610.05,1344.07 r270 top value=499
R44 "CRCW060310K0FKEA" 0603 4167.57,982.04 r180 top value=10.0k
R45 "CRCW060340K2FKEA" 0603 4132.68,1145.34 r90 top value=40.2k
R46 "CRCW06032K00FKEA" 0603 2543.68,1345.58 r270 top value=2.00k
R47 "CRCW080531R6FKEA" 0805_HV 2102.24,1409.23 r90 top value=31.6
R48 "CRCW06031K00FKEA" 0603 4032.73,1244.3 r0 top value=1.00k
R49 "CRCW0805121RFKEA" 0805_HV 2044.75,1553.58 r0 top value=121
R50 "RC0603FR-073KL" 0603 2592.97,1955.17 r90 top value=3.00k
R51 "RC0603FR-0727K4L" 0603 2296.06,1239.75 r90 top value=27.4k
R52 "ERJ-8CWFR050V" 1206 2813.82,1975.24 r0 top value=0.05
R53 "CRCW060310K5FKEA" 0603 4198.17,1145.34 r270 top value=10.5k
R54 "CRCW060342K2FKEA" 0603 2293.68,1378.31 r90 top value=42.2k
R55 "CRCW0603499KFKEA" 0603 2356.44,1378.99 r90 top value=499k
R56 "CRCW060310K0FKEA" 0603 4079.5,761.54 r0 bottom value=10.0k
R57 "CRCW060310K0FKEA" 0603 4077.72,544.2 r0 bottom value=10.0k
R58 "CRCW060310K0FKEA" 0603 4086.83,329.52 r0 bottom value=10.0k
R59 "CRCW060310K0FKEA" 0603 4079.5,761.54 r0 top value=10.0k
R60 "CRCW060310K0FKEA" 0603 4080.65,544.2 r0 top value=10.0k
R61 "CRCW060310K0FKEA" 0603 4089.76,329.52 r0 top value=10.0k
R62 "CRCW060310K0FKEA" 0603L 3530.4,755.76 r180 top value=10.0k
R63 "CRCW060310K0FKEA" 0603L 3530.4,545.54 r180 top value=10.0k
R64 "CRCW060310K0FKEA" 0603L 3525.06,329.56 r180 top value=10.0k
SH-J1 "60900213421" Wurth_60900213421 4526.26,400.99 r90 top
SH-J2 "60900213421" Wurth_60900213421 2228.58,2352.36 r180 top
SH-J3 "60900213421" Wurth_60900213421 2300.83,2116.01 r180 top
SH-J4 "60900213421" Wurth_60900213421 2010.68,1988.09 r90 top
SH-J5 "60900213421" Wurth_60900213421 6719.4,188.44 r90 top
SH-J6 "60900213421" Wurth_60900213421 6975.31,188.44 r90 top
SH-J7 "60900213421" Wurth_60900213421 7221.37,188.44 r90 top
T1 "7490220122" Wurth_7490220122 412.6,1789.72 r270 top value=350uH
T2 "750313355" FP-750313355_SMT_XFRMR_29MM08_23MM1-MFG 3863.6,1903.28 r0 top
TP1 "PAIR12" Keystone5010 1446.85,1609.54 r0 top
TP2 "PAIR36" Keystone5010 1446.85,1283.01 r0 top
TP3 "PAIR45" Keystone5010 1456.69,952.76 r0 top
TP4 "PAIR78" Keystone5010 1456.69,561.02 r0 top
TP5 "EARTH" Keystone5011 848.55,321.28 r0 top
TP6 "Adapter+" Keystone5000 2017.72,3543.31 r90 top
TP7 "APD" Keystone5002 2033.74,2236.79 r90 top
TP8 "Adapter-" Keystone5001 1555.12,3543.31 r90 top
TP9 "VDD" Keystone5000 2203.42,3120.73 r90 top
TP10 "PPD" Keystone5002 1962.89,927.16 r90 top
TP11 "VSS" Keystone5001 1673.23,2047.24 r90 top
TP12 "LINEUV" Keystone5000 2805.97,1185.01 r90 top
TP13 "VDD" Keystone5000 1692.91,2563.86 r90 top
TP14 "VOUT" Keystone5000 5472.44,1534.12 r180 top
TP15 "GATE_P" Keystone5000 4924.55,2095.04 r90 top
TP16 "DRAIN_P" Keystone5000 4340.55,1200.79 r90 top
TP17 "GATE_S" Keystone5000 4703.28,2645.64 r90 top
TP18 "GND" Keystone5001 4204.5,1358.27 r90 top
TP19 "GND" Keystone5001 4526.26,2967.46 r90 top
TP20 "GND" Keystone5001 4708.11,160.01 r90 top
TP21 "DRAIN_S" Keystone5000 4372.51,2645.64 r90 top
TP22 "SST" Keystone5002 2556.05,922.18 r90 top
TP23 "DRAIN2" Keystone5000 3395.67,1113.88 r90 top
TP24 "VCC" Keystone5000 3326.77,931.13 r90 top
TP25 "SST" Keystone5002 2746.06,2103.27 r90 top
TP26 "SST" Keystone5002 2279.12,2490.72 r90 top
TP27 "GATE2" Keystone5000 3222.52,1141.73 r90 top
TP28 "DRAIN" Keystone5000 3459.81,2510.73 r90 top
TP29 "RTN" Keystone5001 3345.38,2773.22 r90 top
TP30 "GAT2" Keystone5000 2988.19,1119.7 r90 top
TP31 "GATE" Keystone5000 2932.03,2120.08 r90 top
TP32 "GATE_Q11" Keystone5000 3082.73,2434.38 r90 top
TP33 "VB" Keystone5002 2740.65,937.12 r90 top
TP34 "TEST (PG)" Keystone5003 4202.53,868.68 r90 top
TP35 "RTN" Keystone5001 3139.74,2988.88 r90 top
TP36 "SOURCE" Keystone5000 3230.1,2569 r90 top
TP37 "COMP" Keystone5002 3601.32,914.63 r90 top
TP38 "VSS" Keystone5001 1734.25,1442.04 r270 top
TP39 "RTN" Keystone5001 2414.67,351.28 r0 top
TP40 "GND" Keystone5001 5474.53,2029.73 r180 top
TP41 "I_STP" Keystone5002 2411.26,918.39 r90 top
TP42 "RTN" Keystone5001 3028.93,353.06 r180 top
TP43 "TLH_O" Keystone5003 4192.38,651.78 r90 top
TP44 "TPH" Keystone5003 3404.21,661.49 r90 top
TP45 "TPL_O" Keystone5003 4184.81,437.27 r90 top
TP46 "TPL" Keystone5003 3409.85,445.54 r90 top
TP47 "BT_O" Keystone5003 4216.94,160.01 r90 top
TP48 "BT" Keystone5003 3404.21,228.91 r90 top
U1 "TPS23730RMT" RMT0045A 2397.53,1619.18 r270 top
U2 "TCMT1107" SOP-4 3808.56,1066.15 r180 top
U3 "TL431IDBVR" DBV0005A_M 4056.07,1354.97 r0 top
U3 "TLV431IDBVR" DBV0005A_N 4056.07,1354.97 r0 top
U4 "FOD817DS" N04C 3800.14,706.69 r0 top
U5 "FOD817DS" N04C 3802.12,495.54 r0 top
U6 "FOD817DS" N04C 3802.12,279.56 r0 top
ZZ1 "This Assembly Note is for PCB labels only" AssemblyNoteLabel 531.5,4389.76 r0 top
ZZ2 "These assemblies are ESD sensitive, ESD precautions shall be observed." AssemblyNote 531.5,4281.5 r0 top
ZZ3 "These assemblies must be clean and free from flux and all contaminants. Use of no clean flux is not acceptable." AssemblyNote 531.5,4202.76 r0 top
ZZ4 "These assemblies must comply with workmanship standards IPC-A-610 Class 2, unless otherwise specified." AssemblyNote 521.65,4124.02 r0 top

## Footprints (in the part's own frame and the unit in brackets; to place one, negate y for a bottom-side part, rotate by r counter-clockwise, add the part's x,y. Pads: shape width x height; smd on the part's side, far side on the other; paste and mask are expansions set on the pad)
0603 [mm] "0603 from SM-752 data"
  rect 1x0.95 smd: 1(-0.8,0) 2(0.8,0)
  silkscreen extent -1.52,-0.69 1.52,0.69, body extent -0.87,-0.47 0.87,0.47, height 1
0603L [mm] "0603 from SM-752 data"
  rect 0.8x0.85 smd: 1(-0.7,0) 2(0.7,0)
  silkscreen extent -0.07,-0.33 0.07,0.33, body extent -0.87,-0.47 0.87,0.47, height 1
0805_HV [mil] "0805 with 30mil clearance between pads"
  rect 50x63 smd: 1(-40,0) 2(40,0)
  silkscreen extent -74,-40 74,40, body extent -43,-29 43,29, height 57
1206 [mm] "1206 from SM-752 data"
  rect 1.3x1.85 smd: 1(-1.45,0) 2(1.45,0)
  silkscreen extent -2.4,-1.21 2.4,1.21, body extent -1.7,-0.9 1.7,0.9, height 1.35
1206_180 [mm] "1206_180"
  rect 1.1x1.6 smd: 1(-1.7,0) 2(1.7,0)
  silkscreen extent -0.9,-1 0.9,1, body extent -1.75,-0.95 1.75,0.95, height 1.8
1210 [mm] "1210 from SM-752 data"
  rect 1.3x2.7 smd: 1(-1.45,0) 2(1.45,0)
  silkscreen extent -2.32,-1.57 2.32,1.57, body extent -1.7,-1.35 1.7,1.35, height 1.35
1210_270 [mm] "1210"
  rect 1.3x2.7 smd: 1(-1.45,0) 2(1.45,0)
  silkscreen extent -2.32,-1.57 2.32,1.57, body extent -1.7,-1.35 1.7,1.35, height 2.7
1808 [mm] "Chip Capacitor, Body 4.6x2.0mm, IPC Medium Density"
  rect 1.4x2.3 smd: 1(-2.1,0) 2(2.1,0)
  silkscreen extent -3.1,-1.45 3.1,1.45, body extent -2.47,-1.2 2.47,1.2, height 2.03
1812_HV [mil] "PRG recommended land pattern"
  rect 60x140 smd: 1(-85,0) 2(85,0)
  silkscreen extent -129,-84 129,84, body extent -94,-67 94,67, height 53
2512 [mm] "Chip Resistor, Body 6.3x3.2mm, IPC Medium Density"
  rect 1.3x3.4 smd: 1(-2.95,0) 2(2.95,0)
  silkscreen extent -1.9,-1.6 1.9,1.6, body extent -3.22,-1.67 3.22,1.67, height 0.71
AssemblyNote [mil] "Assembly Note"
AssemblyNoteLabel [mil] "Assembly Note for PCB Labels"
Bumpon_SJ5003Transparent [mil] "3M Hemispherical Bumpon transparent"
  round 1 on Mech4: 0(0,0)
  silkscreen extent -228,-228 228,228, body extent -219,-219 219,219, height 197
CE_Mark_5mm [mil] "Minimum text height for CE Mark"
  silkscreen extent -138,-98 138,98
CONN_PEC02SAAN [mm] "SULLINS"
  rrect7% 1.5x1.5 hole 1.016: 1(-1.27,0)
  round 1.5 hole 1.016: 2(1.27,0)
  silkscreen extent -2.54,-1.52 2.54,1.27, body extent -2.54,-1.27 2.54,1.27, height 8.38
DBV0005A_M [mm] "SOT23, 5-Leads, Body 2.9x1.6mm, Pitch 0.95mm, Lead Span 2.8mm, IPC Low Density"
  rrect15% 1.2x0.65 smd: 1(-1.475,0.95) 2(-1.475,0) 3(-1.475,-0.95) 4(1.475,-0.95) 5(1.475,0.95)
  silkscreen extent -0.15,-1.55 0.15,1.55, body extent -1.42,-1.46 1.42,1.46, height 1.09
DBV0005A_N [mm] "SOT23, 5-Leads, Body 2.9x1.6mm, Pitch 0.95mm, Lead Span 2.8mm, IPC Medium Density"
  rrect17% 1x0.6 smd: 1(-1.375,0.95) 2(-1.375,0) 3(-1.375,-0.95) 4(1.375,-0.95) 5(1.375,0.95)
  silkscreen extent -0.25,-1.55 0.25,1.55, body extent -1.42,-1.46 1.42,1.46, height 1.09
DQJ0008A [mm] "SMD, 8-Leads, Body 5.75x4.9mm"
  rrect39% 0.91x0.51 smd paste-0.05 mask-0.05: 1(-2.795,1.905) 2(-2.795,0.635) 3(-2.795,-0.635) 4(-2.795,-1.905) 5(2.795,-1.905) 6(2.795,-0.635) 7(2.795,0.635) 8(2.795,1.905)
  rrect8% 1.58x1.25 on Top Paste: 9(-0.38,1.45) 9(-0.38,0) 9(-0.38,-1.45) 9(1.4,1.45) 9(1.4,0) 9(1.4,-1.45)
  rrect3% 3.48x4.47 on Top Solder: 9(0.55,0)
  rrect2% 4.49x4.57 smd paste-2.5 mask-2.5: 9(1.005,0)
  silkscreen extent -3,-2.6 3,2.6, body extent -3.13,-2.45 3.13,2.45, height 1.15
DQK0006C [mm] "WSON"
  rrect12% 0.9x0.86 on Top Paste: 0(0,0.325)
  rrect34% 0.7x0.29 on Top Paste: 0(0.095,-0.65)
  rrect33% 0.45x0.3 smd: 1(-0.975,0.65) 2(-0.975,0) 3(-0.975,-0.65) 4(0.975,-0.65) 5(0.975,0) 6(0.975,0.65)
  rrect33% 0.75x0.3 smd paste-0.15: 7(0.095,-0.65)
  rrect11% 1x0.95 smd paste-0.5: 8(0,0.325)
  silkscreen extent -1.15,-1.15 1.15,1.15, body extent -1,-1 1,1, height 0.82
FCC_disclaimer [mil]
Fiducial10-20 [mm]
  round 1 smd mask+0.5: 1(0,0)
  Top Layer keep-out circle w1.178: c0,0 r0.5
FP-750313355_SMT_XFRMR_29MM08_23MM1-MFG [mm]
  rrect8% 3.05x1.27 smd paste+0 mask+0: 1(-13.26,7.5) 2(-13.26,4.5) 3(-13.26,1.5) 4(-13.26,-1.5) 5(-13.26,-4.5) 6(-13.26,-7.5) 7(13.26,-7.5) 8(13.26,-4.5) 9(13.26,-1.5) 10(13.26,1.5) 11(13.26,4.5) 12(13.26,7.5)
  silkscreen extent -15.46,-11.56 14.54,11.56, body extent -14.88,-11.66 14.88,11.66, height 0.25
Keystone5000 [mil] "For Keystone 500x miniature loop terminals"
  round 80 hole 40: 1(0,0)
  silkscreen extent -52,-52 52,52, body extent -49,-49 49,49, height 182
Keystone5001 [mil] "For Keystone 500x miniature loop terminals"
  round 80 hole 40: 1(0,0)
  silkscreen extent -52,-52 52,52, body extent -49,-49 49,49, height 182
Keystone5002 [mil] "For Keystone 500x miniature loop terminals"
  round 80 hole 40: 1(0,0)
  silkscreen extent -52,-52 52,52, body extent -49,-49 49,49, height 182
Keystone5003 [mil] "For Keystone 500x miniature loop terminals"
  round 80 hole 40: 1(0,0)
  silkscreen extent -52,-52 52,52, body extent -49,-49 49,49, height 182
Keystone5010 [mil] "Keystone Multipurpose loops"
  round 87 hole 63: 1(0,0)
  silkscreen extent -70,-70 70,70, body extent -63,-63 63,62, height 319
Keystone5011 [mil] "Keystone Multipurpose loops"
  round 87 hole 63: 1(0,0)
  silkscreen extent -70,-70 70,70, body extent -63,-63 63,62, height 319
Label_650x200 [mil] "Thermal Transfer Label"
  round 1 on Mech13: 0(0,0)
  silkscreen extent -325,-100 325,100, body extent -325,-100 325,100, height 1
MLP08S [mm] "Fairchild MLP08S recommended land pattern"
  rect 0.7x0.42 smd mask+0.051: 1(-1.4,0.975) 2(-1.4,0.325) 3(-1.4,-0.325) 4(-1.4,-0.975) 5(1.4,-0.975) 6(1.4,-0.325) 7(1.4,0.325) 8(1.4,0.975)
  Top Layer region: -0.4,-1.185 1.3,-1.185 1.3,1.185 -0.4,1.185
  silkscreen extent -1.8,-1.8 1.8,1.8, body extent -1.67,-1.67 1.67,1.67, height 0.81
MOLEX_39357-0002 [mm] "Terminal Block, 3.5 mm, 2x1, TH"
  rect 1.6x1.6 hole 1.1: 1(-1.75,0)
  round 1.6 hole 1.1: 2(1.75,0)
  silkscreen extent -3.86,-3.45 3.5,3.84, body extent -3.55,-3.45 3.56,3.84, height 8.51
N04C [mm] "FAIRCHILD"
  rect 1.3x1.5 smd mask+0.065: 1(-4.587,1.27) 2(-4.612,-1.27) 3(4.588,-1.27) 4(4.613,1.27)
  silkscreen extent -3.56,-2.3 3.56,2.72, body extent -5.08,-2.3 5.08,2.29, height 3.87
Panasonic_G [mm] "SMD, 2-Leads, Dia 10mm"
  rect 4.1x2 smd: 1(-4.35,0) 2(4.35,0)
  silkscreen extent -5.25,-5.25 5.25,5.25, body extent -5.25,-5.25 5.25,5.25, height 10.51
PG-TDSON-8 [mm] "Infineon recommended land pattern"
  rect 1.2x0.65 smd: 1(-2.825,1.905) 2(-2.825,0.635) 3(-2.825,-0.635) 4(-2.825,-1.905)
  rect 0.5x0.7 smd: 5(3.175,-2) 6(3.175,-0.675) 7(3.175,0.675) 8(3.175,2)
  rect 4.5x4.7 smd paste-2.25: 9(0.675,0)
  silkscreen extent -3.74,-3 3.74,3, body extent -3.18,-2.89 3.17,2.9, height 1.1
RMT0045A [mm] "VQFN-45"
  rrect50% 0.6x0.2 smd: 1(-2.4,2.6) 2(-2.4,2.2) 3(-2.4,1.8) 4(-2.4,1.4) 5(-2.4,1) 6(-2.4,0.6) 7(-2.4,0.2) 8(-2.4,-0.2) 9(-2.4,-0.6) 10(-2.4,-1.4) 11(-2.4,-1.8) 12(-2.4,-2.2) 13(-2.4,-2.6) 23(2.4,-2.6) 24(2.4,-2.2) 25(2.4,-1.8) 26(2.4,-1.4) 27(2.4,-1) 28(2.4,-0.6) 29(2.4,-0.2) 30(2.4,0.6) 31(2.4,1) 32(2.4,1.4) 33(2.4,1.8) 34(2.4,2.2) 35(2.4,2.6)
  rrect50% 0.2x0.6 smd: 14(-1.8,-3.4) 15(-1.4,-3.4) 16(-1,-3.4) 17(-0.6,-3.4) 18(-0.2,-3.4) 19(0.2,-3.4) 20(0.6,-3.4) 21(1,-3.4) 22(1.4,-3.4) 36(1.8,3.4) 37(1.4,3.4) 38(1,3.4) 39(0.6,3.4) 40(0.2,3.4) 41(-0.2,3.4) 42(-0.6,3.4) 43(-1,3.4) 44(-1.4,3.4) 45(-1.8,3.4)
  rrect5% 3.7x2.1 smd paste-2: 46(0,1.4)
  rrect5% 2.9x2.15 smd paste-2: 47(0,-1.375)
  body extent -2.55,-3.55 2.55,3.55, height 1.01
SM_RADIAL_6.3AMM [mm] "Nichicon 6.3x5.8"
  rect 3.5x1.6 smd: 1(-2.7,0) 2(2.7,0)
  silkscreen extent -3.3,-3.29 3.3,3.31, body extent -3.5,-3.3 3.5,3.3, height 6.11
SM_RADIAL_8MM [mm] "Nichicon 8x10"
  rect 3.5x2.5 smd: 1(-3.25,0) 2(3.25,0)
  silkscreen extent -4.25,-4.25 4.25,4.25, body extent -4.25,-4.25 4.25,4.25, height 10.5
SM_RADIAL_H13 [mm] "12.5 x 13.5mm:  Panasonic H13"
  rect 5.7x2 smd: 1(-4.85,0) 2(4.85,0)
  silkscreen extent -6.85,-6.85 6.85,6.85, body extent -6.85,-6.85 6.85,6.85, height 14
SMA [mm] "Molded Diode, 2-Leads, Body 4.3x2.6mm, IPC Medium Density, based on OnSemi component dimensions and land pattern"
  rect 2x2 smd: 1(-2,0) 2(2,0)
  silkscreen extent -3.66,-1.57 2.79,1.57, body extent -2.6,-1.3 2.6,1.3, height 2.42
SMB [mil] "Molded Diode, 2-Leads, Body 5.4x3.6mm, IPC Medium Density, based on OnSemi component dimensions"
  rect 85x107.99 smd: 1(-87.01,0) 2(87.01,0)
  silkscreen extent -155,-82 125,82, body extent -106,-71 106,71, height 91
SMC [mil] "Molded Diode, 2-Leads, Body 6.9x5.8mm, IPC Medium Density, based on OnSemi component dimensions and land patterns"
  rect 110x150 smd: 1(-140.49,0) 2(140.49,0)
  silkscreen extent -221,-123 189,124, body extent -156,-116 157,116, height 91
SOD-123 [mm] "On Semi recommended land pattern"
  rect 0.915x1.22 smd: 1(-1.637,0) 2(1.637,0)
  silkscreen extent -2.74,-1.17 2.03,1.17, body extent -1.93,-0.9 1.93,0.9, height 1.35
SOIC-8 [mm] "duplicate of SO-8.  SOIC, 8-Leads, Body 5.0x4.0mm (max), Pitch 1.27mm, IPC Medium Density"
  rrect17% 1.45x0.6 smd: 1(-2.725,1.905) 2(-2.725,0.635) 3(-2.725,-0.635) 4(-2.725,-1.905) 5(2.725,-1.905) 6(2.725,-0.635) 7(2.725,0.635) 8(2.725,1.905)
  silkscreen extent -3.5,-2.5 0.9,2.5, body extent -3,-2.45 3,2.45, height 1.63
SOP-4 [mm] "Vishay Half Pitch Mini-Flat Package"
  rect 1.3x0.9 smd: 1(-3.15,0.635) 2(-3.15,-0.635) 3(3.15,-0.635) 4(3.15,0.635)
  silkscreen extent -2.2,-1.41 2.2,1.39, body extent -3.5,-1.4 3.5,1.4, height 2.12
SOT-23 [mm] "SOT23, 3-Leads, Body 2.9x1.3mm, Pitch 0.95mm, Lead Span 2.5mm, IPC Medium Density"
  rrect50% 1x0.6 smd: 1(-1.2,0.95) 2(-1.2,-0.95) 3(1.2,0)
  silkscreen extent -1.63,-1.5 0.7,1.5, body extent -1.16,-1.45 1.21,1.45, height 1
SOT-89-3 [mm] "SOT, 3-Leads, Body 4.6 x 2.6 mm, Pitch 1.5mm"
  rect 1.4x0.9 smd: 1(-1.9,1.5) 3(-1.9,-1.5)
  rect 1.8x0.9 smd: 2(-1.7,0)
  oct 3.4x1.9 smd: 4(0.9,0)
  silkscreen extent -1.3,-2.45 1.33,2.45, body extent -2.42,-2.28 1.83,2.32, height 1.62
TE_5-146278-2 [mm] "TE CONNECTIVITY"
  rect 1.65x1.65 hole 1: 1(-1.27,0)
  round 1.65 hole 1: 2(1.27,0)
  silkscreen extent -2.92,-1.27 2.54,1.27, body extent -2.41,-1.17 2.41,1.17, height 8.13
TE_5-146278-3 [mm] "TE CONNECTIVITY"
  rect 1.65x1.65 hole 1: 1(-2.54,0)
  round 1.65 hole 1: 2(0,0) 3(2.54,0)
  silkscreen extent -4.19,-1.27 3.81,1.27, body extent -3.68,-1.17 3.68,1.17, height 8.13
TEC_1-406541-1 [mm] "TE Connectivity"
  round 1.4 hole 0.89: 1(3.56,-0.18) 2(2.54,1.6) 3(1.52,-0.18) 4(0.5,1.6) 5(-0.52,-0.18) 6(-1.54,1.6) 7(-2.56,-0.18) 8(-3.58,1.6)
  round 2.1 hole 1.57: 9(8.12,0.71) 10(-8.14,0.71)
  round 3.759 hole 3.251: 11(6.34,-2.72) 12(-6.36,-2.72)
  silkscreen extent -9.69,-8 9.69,8.06, body extent -9.33,-8 9.31,7.75, height 14.8
TERM_BLK_ED555-2DS [mil]
  rrect4% 100x100 hole 50: 1(0,0)
  round 100 hole 50: 2(138,0)
  silkscreen extent -93,-161 215,113, body extent -69,-150 207,106, height 323
TRANS_Fairchild_PQFN08A [mm] "Fairchild PQFN08A recommended land pattern"
  rect 1.27x0.61 smd: 1(-2.67,1.905) 2(-2.67,0.635) 3(-2.67,-0.635) 4(-2.67,-1.905) 5(2.67,-1.905) 6(2.67,-0.635) 7(2.67,0.635) 8(2.67,1.905)
  Top Layer region: -1.215,-2.55 2.535,-2.55 2.535,2.55 -1.215,2.55
  silkscreen extent -3.2,-2.7 3.2,2.7, body extent -3.05,-2.55 3.05,2.55, height 1.11
VSMP_0603 [mm] "Recommended by Vishay"
  rect 0.905x0.78 smd: 1(-0.842,0) 2(0.843,0)
  silkscreen extent -1.6,-0.7 1.6,0.7, body extent -0.86,-0.47 0.86,0.47, height 0.64
WE-HC6 [mm] "Wurth Electronik recommended land pattern"
  rect 3.85x4 smd: 1(-3.825,0) 2(3.825,0)
  silkscreen extent -6.2,-6.2 6.2,6.2, body extent -5.76,-5.36 5.74,5.34, height 5
WE-HCB_1890 [mm] "WURTH ELEKTRONIK"
  rect 6x6 smd: 1(-6.65,0) 2(6.65,0)
  silkscreen extent -9.7,-9.4 9.7,9.4, body extent -9.65,-9.35 9.65,9.35, height 9.2
WE-PD2-L [mil] "WE, Inductor"
  round 60 smd: 1(-98.43,0) 2(98.43,0)
  Top Layer region: -39.37,-147.64 -39.37,147.64 -139.76,147.64 -157.48,129.92 -157.48,-125.98 -135.83,-147.64
  Top Layer region: 39.37,147.64 39.37,-147.64 139.76,-147.64 157.48,-129.92 157.48,125.98 135.83,147.64
  silkscreen extent -20,-161 30,161, body extent -157,-144 159,144, height 217
WE-SL5 [mm] "SMD, 4-Leads, Body 8.7x10mm"
  rect 2.7x2.7 smd: 1(-3.11,3.81) 2(-3.11,-3.81) 3(3.11,-3.81) 4(3.11,3.81)
  silkscreen extent -4.35,-5 4.35,5.4, body extent -4.35,-5 4.35,5, height 6
WEEE_Minimum [mil] "WEEElie bin"
  silkscreen extent -95,-172 99,104
WL-SMCW_YELLOW [mm] "WURTH"
  rect 0.8x0.8 smd: 1(-0.8,0) 2(0.8,0)
  silkscreen extent -1.9,-0.8 1.2,0.8, body extent -0.85,-0.45 0.85,0.45, height 0.8
Wurth_7490220122 [mm] "SMD, 24-Leads, Body 14.7x18.29mm"
  rect 2.29x0.76 smd: 1(-7.24,6.985) 2(-7.24,5.715) 3(-7.24,4.445) 4(-7.24,3.175) 5(-7.24,1.905) 6(-7.24,0.635) 7(-7.24,-0.635) 8(-7.24,-1.905) 9(-7.24,-3.175) 10(-7.24,-4.445) 11(-7.24,-5.715) 12(-7.24,-6.985) 13(7.24,-6.985) 14(7.24,-5.715) 15(7.24,-4.445) 16(7.24,-3.175) 17(7.24,-1.905) 18(7.24,-0.635) 19(7.24,0.635) 20(7.24,1.905) 21(7.24,3.175) 22(7.24,4.445) 23(7.24,5.715) 24(7.24,6.985)
  silkscreen extent -7.7,-9.15 7.35,9.15, body extent -7.35,-9.15 7.35,9.15, height 8.81
Wurth_60900213421 [mil] "Shunt, 2.54mm, Black"
  round 1 on Mech3: 0(0,0)
  body extent -98,-48 98,48, height 338

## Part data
C1 C2 C3 C4: library part CMP-0007082-4, "CAP, CERM, 0.01 uF, 100 V, +/- 10%, X7R, AEC-Q200 Grade 1, 0603", Cap_Case=0603, Manufacturer=TDK, Supplier Part Number 1=445-5812-1-ND, TempCo=X7R, Tolerance_%=10%, Value1="0.235428 ohm", Value2=100V, ValueDisplayed=0.01uF
C5 C6: library part CMP-0009436-2, "CAP, CERM, 1000 pF, 2000 V, +/- 10%, X7R, 1808", Cap_Case=1808, Manufacturer=MuRata, Supplier Part Number 1=490-8145-1-ND, TempCo=X7R, Tolerance_%=10%, Value1=Unknown, Value2=2000V, ValueDisplayed=1000pF
C7 C8 C9 C10: library part CMP-0007053-4, "CAP, CERM, 1000 pF, 100 V, +/- 10%, X7R, 0603", Cap_Case=0603, Manufacturer=TDK, Supplier Part Number 1=445-1298-1-ND, TempCo=X7R, Tolerance_%=10%, Value1=Unknown, Value2=100V, ValueDisplayed=1000pF
C11: library part CMP-0007557-2, "CAP, CERM, 470 pF, 100 V, +/- 10%, X7R, 0805", Cap_Case=0805, Manufacturer=AVX, Supplier Part Number 1=478-1350-1-ND, TempCo=X7R, Tolerance_%=10%, Value1="0.454 ohm", Value2=100V, ValueDisplayed=470pF
C12 C13 C14 C15: library part CMP-0006823-4, "CAP, CERM, 330 pF, 50 V, +/- 5%, C0G/NP0, 0603", Cap_Case=0603, Manufacturer="Wurth Elektronik", Supplier Part Number 1=710-885012006060, TempCo=C0G/NP0, Tolerance_%=5%, Value1=Unknown, Value2=50V, ValueDisplayed=330pF
C16 C18: library part CMP-0009358-2, "CAP, CERM, 2200 pF, 2000 V, +/- 10%, X7R, 1812", Cap_Case=1812, Manufacturer=TDK, Supplier Part Number 1=445-2389-1-ND, TempCo=X7R, Tolerance_%=10%, Value1=Unknown, Value2=2000V, ValueDisplayed=2200pF
C17 C37: library part CMP-0008768-2, "CAP, CERM, 0.047 uF, 100 V, +/- 10%, X7R, AEC-Q200 Grade 1, 1206", Cap_Case=1206, Manufacturer=TDK, Supplier Part Number 1=445-5838-1-ND, TempCo=X7R, Tolerance_%=10%, Value1="0.065629 ohm", Value2=100V, ValueDisplayed=0.047uF
C19: library part CMP-0008483-2, "CAP, CERM, 1000 pF, 100 V, +/- 10%, X7R, 1206", Cap_Case=1206, Manufacturer=AVX, Supplier Part Number 1=478-1517-1-ND, TempCo=X7R, Tolerance_%=10%, Value1="0.427 ohm", Value2=100V, ValueDisplayed=1000pF
C20 C34: library part CMP-0008881-2, "CAP, CERM, 0.1 uF, 100 V, +/- 10%, X7R, 1206", Cap_Case=1206, Manufacturer=MuRata, Supplier Part Number 1=490-3364-1-ND, TempCo=X7R, Tolerance_%=10%, Value1=Unknown, Value2=100V, ValueDisplayed=0.1uF
C21: library part CMP-0011226-2, "CAP, AL, 68 uF, 100 V, +/- 20%, 0.32 ohm, AEC-Q200 Grade 2, SMD", Cap_Case=H13, Manufacturer=Panasonic, Supplier Part Number 1=PCE3498CT-ND, Tolerance_%=20%, Value1="0.32 ohm", Value2=100V, ValueDisplayed=68uF
C22 C23 C24: library part CMP-0009232-2, "CAP, CERM, 2.2 uF, 100 V, +/- 10%, X7R, 1210", Cap_Case=1210, Manufacturer=MuRata, Supplier Part Number 1=490-3385-1-ND, TempCo=X7R, Tolerance_%=10%, Value1="0.007 ohm", Value2=100V, ValueDisplayed=2.2uF
C25: library part CMP-0008363-2, "CAP, CERM, 0.1 uF, 100 V, +/- 10%, X7R, 0805", Cap_Case=0805, Manufacturer=MuRata, Supplier Part Number 1=490-12005-1-ND, TempCo=X7R, Tolerance_%=10%, Value1=Unknown, Value2=100V, ValueDisplayed=0.1uF
C26 C31 C43: library part CMP-0006751-4, "CAP, CERM, 100 pF, 25 V, +/- 10%, X7R, 0603", Cap_Case=0603, Manufacturer=AVX, Supplier Part Number 1=55J3899, TempCo=X7R, Tolerance_%=10%, Value1=Unknown, Value2=25V, ValueDisplayed=100pF
C27 C29: library part CMP-0083812-1, "CAP, CERM, 100 µF, 6.3 V,+/- 20%, X7S, 1210", Cap_Case=1210, Manufacturer=MuRata, TempCo=X7S, Tolerance_%=20%, Value2=6.3V, ValueDisplayed=100µF
C27 C29: library part CMP-0085817-1, "CAP, CERM, 22 µF, 35 V,+/- 20%, X5R, 1210", Cap_Case=1210, Manufacturer="Taiyo Yuden", TempCo=X5R, Tolerance_%=20%, Value2=35V, ValueDisplayed=22µF
C28: library part CMP-0011104-1, "CAP, AL, 470 uF, 6.3 V, +/- 20%, 0.17 ohm, SMD", Cap_Case=8x10, Manufacturer=Nichicon, Supplier Part Number 1=493-2238-1-ND, Tolerance_%=20%, Value1="0.17 ohm", Value2=6.3V, ValueDisplayed=470uF
C28: library part CMP-0012085-3, "CAP, Aluminum Polymer, 39 uF, 16 V, +/- 20%, 0.05 ohm, 6.3x5.8 SMD", Cap_Case=6.6x6.6x5.9, Manufacturer=Panasonic, Tolerance_%=20%, Value1="0.05 ohm", Value2=16V, ValueDisplayed=39uF
C30: library part CMP-0010735-1, "CAP, AL, 560 uF, 25 V, +/- 20%, 0.08 ohm, AEC-Q200 Grade 2, SMD", Cap_Case=10x10.2mm, Manufacturer=Panasonic, Supplier Part Number 1=PCE4441CT-ND, Tolerance_%=20%, Value1="0.08 ohm", Value2=25V, ValueDisplayed=560uF
C32: library part CMP-0008336-2, "CAP, CERM, 1 uF, 25 V, +/- 10%, X7R, 0805", Cap_Case=0805, Manufacturer=MuRata, Supplier Part Number 1=GRM21BR71E105KA99L-ND, TempCo=X7R, Tolerance_%=10%, Value1=Unknown, Value2=25V, ValueDisplayed=1uF
C33: library part CMP-0008975-2, "CAP, CERM, 0.047 uF, 250 V, +/- 10%, X7R, 1206", Cap_Case=1206, Manufacturer=MuRata, Supplier Part Number 1=490-3538-1-ND, TempCo=X7R, Tolerance_%=10%, Value1=Unknown, Value2=250V, ValueDisplayed=0.047uF
C35: library part CMP-0007457-4, "CAP, CERM, 0.047 uF, 50 V, +/- 10%, X7R, 0603", Cap_Case=0603, Manufacturer=MuRata, Supplier Part Number 1=490-3287-1-ND, TempCo=X7R, Tolerance_%=10%, Value1=Unknown, Value2=50V, ValueDisplayed=0.047uF
C36: library part CMP-0007081-4, "CAP, CERM, 1000 pF, 100 V, +/- 10%, X7R, AEC-Q200 Grade 1, 0603", Cap_Case=0603, Manufacturer=TDK, Supplier Part Number 1=445-5806-1-ND, TempCo=X7R, Tolerance_%=10%, Value1="1.97137 ohm", Value2=100V, ValueDisplayed=1000pF
C38: library part CMP-0008021-2, "CAP, CERM, 0.1 uF, 50 V, +/- 10%, X7R, AEC-Q200 Grade 1, 0805", Cap_Case=0805, Manufacturer=MuRata, Supplier Part Number 1=490-8049-1-ND, TempCo=X7R, Tolerance_%=10%, Value1=Unknown, Value2=50V, ValueDisplayed=0.1uF
C39: library part CMP-0007835-2, "CAP, CERM, 0.22 uF, 50 V, +/- 10%, X5R, 0805", Cap_Case=0805, Manufacturer=TDK, Supplier Part Number 1=445-14405-1-ND, TempCo=X5R, Tolerance_%=10%, Value1="0.016949 ohm", Value2=50V, ValueDisplayed=0.22uF
C40: library part CMP-0007077-5, "CAP, CERM, 0.1 uF, 25 V, +/- 10%, X7R, AEC-Q200 Grade 1, 0603", Cap_Case=0603, Manufacturer=TDK, Supplier Part Number 1=445-5667-1-ND, TempCo=X7R, Tolerance_%=10%, Value1=Unknown, Value2=25V, ValueDisplayed=0.1uF
C41: library part CMP-0006897-4, "CAP, CERM, 2200 pF, 50 V, +/- 10%, X7R, 0603", Cap_Case=0603, Manufacturer=Kemet, Supplier Part Number 1=1362428, TempCo=X7R, Tolerance_%=10%, Value1=Unknown, Value2=50V, ValueDisplayed=2200pF
C42: library part CMP-0006856-6, "CAP, CERM, 0.1 uF, 25 V, +/- 5%, X7R, 0603", Cap_Case=0603, Manufacturer=Kemet, Supplier Part Number 1=399-1282-1-ND, TempCo=X7R, Tolerance_%=5%, Value1=Unknown, Value2=25V, ValueDisplayed=0.1uF
C44: library part CMP-0007400-4, "CAP, CERM, 0.068 uF, 16 V, +/- 10%, X7R, 0603", Cap_Case=0603, Manufacturer=MuRata, Supplier Part Number 1=490-1531-1-ND, TempCo=X7R, Tolerance_%=10%, Value1=Unknown, Value2=16V, ValueDisplayed=0.068uF
C45: library part CMP-0007453-4, "CAP, CERM, 3900 pF, 50 V, +/- 10%, X7R, 0603", Cap_Case=0603, Manufacturer=MuRata, Supplier Part Number 1=490-1504-1-ND, TempCo=X7R, Tolerance_%=10%, Value1=Unknown, Value2=50V, ValueDisplayed=3900pF
C46: library part CMP-0007220-4, "CAP, CERM, 47 pF, 50 V, +/- 5%, C0G/NP0, 0603", Cap_Case=0603, Manufacturer=MuRata, Supplier Part Number 1=490-1419-1-ND, TempCo=C0G/NP0, Tolerance_%=5%, Value1=Unknown, Value2=50V, ValueDisplayed=47pF
C47: library part CMP-0007873-2, "CAP, CERM, 1 uF, 50 V, +/- 10%, X7R, 0805", Cap_Case=0805, Manufacturer=TDK, Supplier Part Number 1=445-7547-1-ND, TempCo=X7R, Tolerance_%=10%, Value1="0.008782 ohm", Value2=50V, ValueDisplayed=1uF
D1 D7 D8 D9 D10: "Diode, Schottky, 100 V, 2 A, SMB", Manufacturer="Diodes Inc.", PartNumber=B2100-13-F, Value1=2A, Value2=0.79V
D2 D3 D4 D5: library part CMP-0028397-2, "Diode, Schottky, 100 V, 2 A, SMB", Manufacturer="Diodes Inc.", Value1=2A, Value2=0.79V
D6: library part CMP-0005583-3, "Diode, TVS, Uni, 58 V, 93.6 Vc, SMB", Manufacturer="Diodes Inc.", Value1=600W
